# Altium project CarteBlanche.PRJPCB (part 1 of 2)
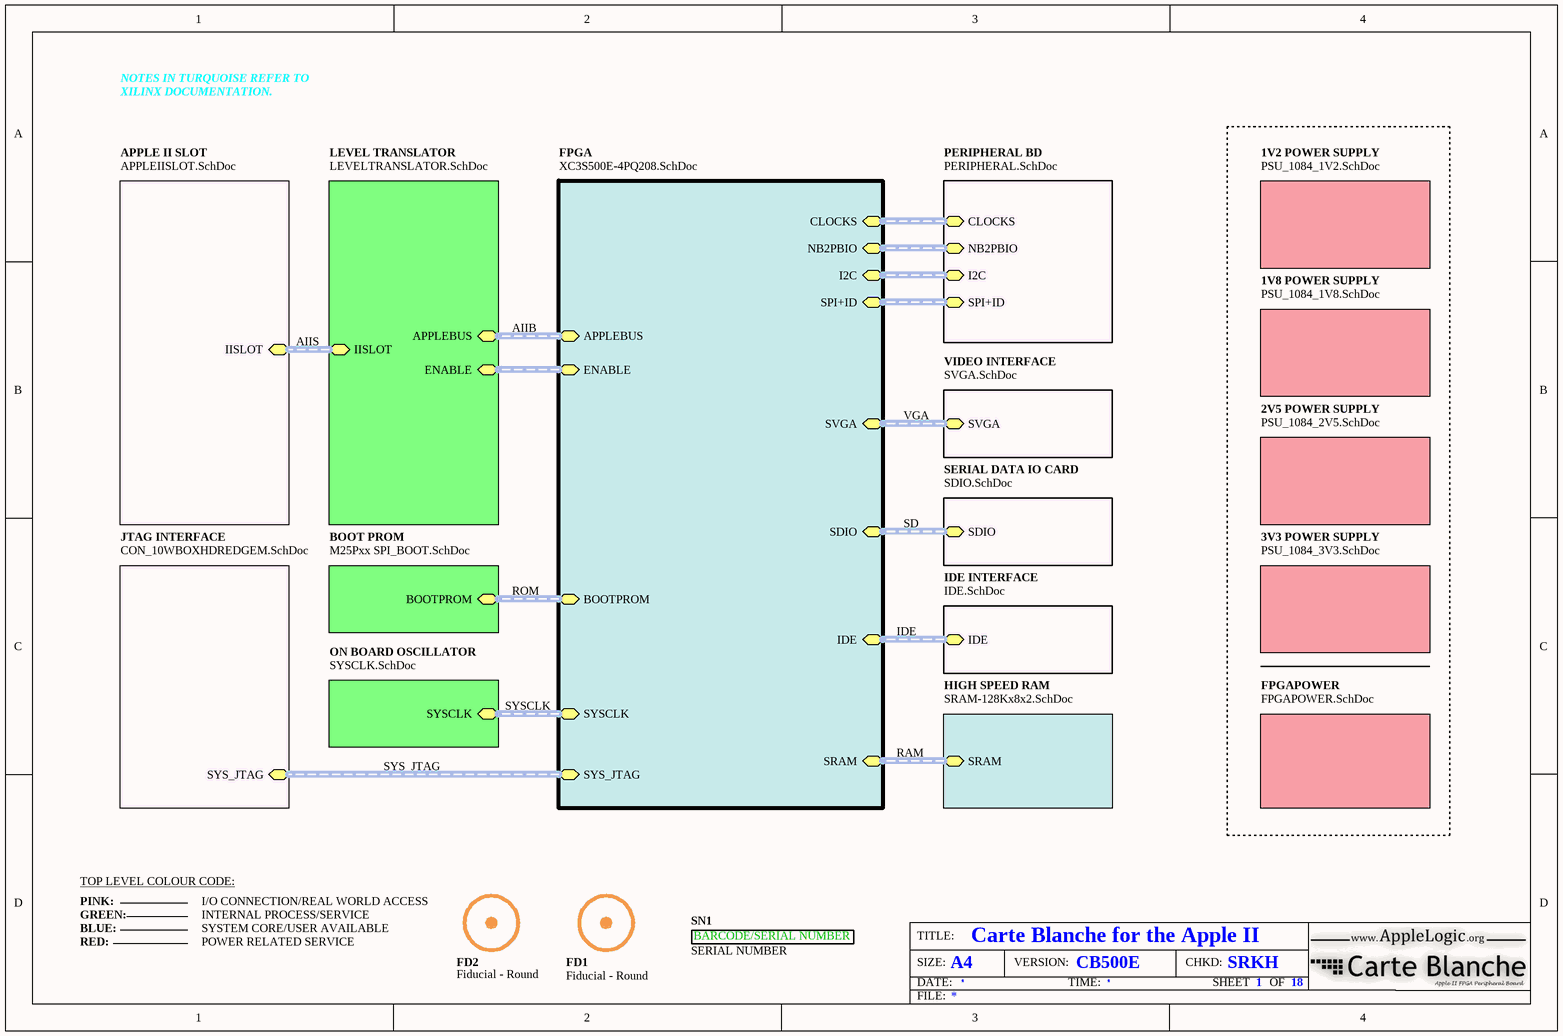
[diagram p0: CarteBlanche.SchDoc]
18 sheets, 155 parts. Net scope: hierarchical (ports join the sheet entries above them; power ports are global).
Sheets:
  CarteBlanche.SchDoc
    APPLE II SLOT = APPLEIISLOT.SchDoc
    JTAG INTERFACE = CON_10WBOXHDREDGEM.SchDoc
    FPGA = XC3S500E-4PQ208.SchDoc
    LEVEL TRANSLATOR = LEVELTRANSLATOR.SchDoc
    PERIPHERAL BD = PERIPHERAL.SchDoc
    1V2 POWER SUPPLY = PSU_1084_1V2.SchDoc
    1V8 POWER SUPPLY = PSU_1084_1V8.SchDoc
    2V5 POWER SUPPLY = PSU_1084_2V5.SchDoc
    3V3 POWER SUPPLY = PSU_1084_3V3.SchDoc
    FPGAPOWER = FPGAPOWER.SchDoc
    HIGH SPEED RAM = SRAM-128Kx8x2.SchDoc
    BOOT PROM = M25Pxx SPI_BOOT.SchDoc
    VIDEO INTERFACE = SVGA.SchDoc
      SVGA DB15 CONNECTOR = SVGAIO.SchDoc
    SERIAL DATA IO CARD = SDIO.SchDoc
    IDE INTERFACE = IDE.SchDoc
    ON BOARD OSCILLATOR = SYSCLK.SchDoc

## Sheet CarteBlanche.SchDoc: Carte Blanche for the Apple II
size A4; PageSetup: Record=PageOptions|CenterHorizontal=True|CenterVertical=True|PrintScale=1.42|XCorrection=1.00|YCorrection=1.00|PrintKind=0|BorderSize=5000000|LeftOffset=0|BottomOffset=0|Orientation=2|PaperLength=1000|PaperWidth=1000|Scale=100|PaperSource=15|PrintQuality=4000|MediaType=1|DitherType=10|PaperKind=A3|PrintScaleMode=1; CheckedBy: SRKH; Author: SRKH; Engineer: SRKH; DocumentNumber: 1; Revision: CB500E; SheetNumber: 1; SheetTotal: 18; DrawnBy: SRKH; Address1: WWW.APPLELOGIC.ORG

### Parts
FD1  Fiducial - Round  [FIDUCIAL ROUND]
FD2  Fiducial - Round  [FIDUCIAL ROUND]
SN1  SERIAL NUMBER  [SERIAL_NO2]  (no BOM)

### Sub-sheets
1V2 POWER SUPPLY = PSU_1084_1V2.SchDoc: no entries
1V8 POWER SUPPLY = PSU_1084_1V8.SchDoc: no entries
2V5 POWER SUPPLY = PSU_1084_2V5.SchDoc: no entries
3V3 POWER SUPPLY = PSU_1084_3V3.SchDoc: no entries
APPLE II SLOT = APPLEIISLOT.SchDoc: IISLOT (harness AIISLOT)
BOOT PROM = M25Pxx SPI_BOOT.SchDoc: BOOTPROM (harness BOOTPROM)
FPGA = XC3S500E-4PQ208.SchDoc: SYS_JTAG (harness SYS_JTAG), APPLEBUS (harness AIISLOT), NB2PBIO (harness NB2PBIO), SPI+ID (harness SPI+ID), I2C (harness I2C), CLOCKS (harness CLOCKS), SRAM (harness SRAM), BOOTPROM (harness BOOTPROM), SVGA (harness SVGA), IDE (harness IDE), SDIO (harness SDIO), SYSCLK (harness SYSCLK), ENABLE (harness ENABLE)
FPGAPOWER = FPGAPOWER.SchDoc: no entries
HIGH SPEED RAM = SRAM-128Kx8x2.SchDoc: SRAM (harness SRAM)
IDE INTERFACE = IDE.SchDoc: IDE (harness IDE)
JTAG INTERFACE = CON_10WBOXHDREDGEM.SchDoc: SYS_JTAG (harness SYS_JTAG)
LEVEL TRANSLATOR = LEVELTRANSLATOR.SchDoc: ENABLE (harness ENABLE), IISLOT (harness AIISLOT), APPLEBUS (harness AIISLOT)
ON BOARD OSCILLATOR = SYSCLK.SchDoc: SYSCLK (harness SYSCLK)
PERIPHERAL BD = PERIPHERAL.SchDoc: NB2PBIO (harness NB2PBIO), SPI+ID (harness SPI+ID), I2C (harness I2C), CLOCKS (harness CLOCKS)
SERIAL DATA IO CARD = SDIO.SchDoc: SDIO (harness SDIO)
VIDEO INTERFACE = SVGA.SchDoc: SVGA (harness SVGA)

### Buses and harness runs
harness AIIB = sheet FPGA/APPLEBUS = sheet LEVEL TRANSLATOR/APPLEBUS
harness AIIS = sheet APPLE II SLOT/IISLOT = sheet LEVEL TRANSLATOR/IISLOT
harness IDE = sheet FPGA/IDE = sheet IDE INTERFACE/IDE
harness RAM = sheet FPGA/SRAM = sheet HIGH SPEED RAM/SRAM
harness ROM = sheet BOOT PROM/BOOTPROM = sheet FPGA/BOOTPROM
harness SD = sheet FPGA/SDIO = sheet SERIAL DATA IO CARD/SDIO
harness sheet FPGA/CLOCKS = sheet PERIPHERAL BD/CLOCKS
harness sheet FPGA/ENABLE = sheet LEVEL TRANSLATOR/ENABLE
harness sheet FPGA/I2C = sheet PERIPHERAL BD/I2C
harness sheet FPGA/NB2PBIO = sheet PERIPHERAL BD/NB2PBIO
harness sheet FPGA/SPI+ID = sheet PERIPHERAL BD/SPI+ID
harness SYS_JTAG = sheet FPGA/SYS_JTAG = sheet JTAG INTERFACE/SYS_JTAG
harness SYSCLK = sheet FPGA/SYSCLK = sheet ON BOARD OSCILLATOR/SYSCLK
harness VGA = sheet FPGA/SVGA = sheet VIDEO INTERFACE/SVGA

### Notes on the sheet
- NOTES IN TURQUOISE REFER TO
- XILINX DOCUMENTATION.
- TOP LEVEL COLOUR CODE:
- PINK:
- GREEN:
- I/O CONNECTION/REAL WORLD ACCESS
- INTERNAL PROCESS/SERVICE
- BLUE:
- RED:
- SYSTEM CORE/USER AVAILABLE
- POWER RELATED SERVICE

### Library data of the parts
FD1 FD2 = FIDUCIAL ROUND: Fiducial - Round 1.5mm Top-Bottom

## Sheet APPLEIISLOT.SchDoc: APPLE II BUS INTERFACE
size A4; PageSetup: Record=PageOptions|CenterHorizontal=True|CenterVertical=True|PrintScale=0.73|XCorrection=1.00|YCorrection=1.00|PrintKind=0|BorderSize=5000000|LeftOffset=0|BottomOffset=0|Orientation=2|PaperLength=1000|PaperWidth=1000|Scale=100|PaperSource=7|PrintQuality=-4|MediaType=1|DitherType=10|PaperKind=A3|PrintScaleMode=1; CheckedBy: SRKH; Author: SRKH; Engineer: SRKH; DocumentNumber: 5; Revision: CB500E; SheetNumber: 5; SheetTotal: 18; DrawnBy: SRKH; Address1: WWW.APPLELOGIC.ORG
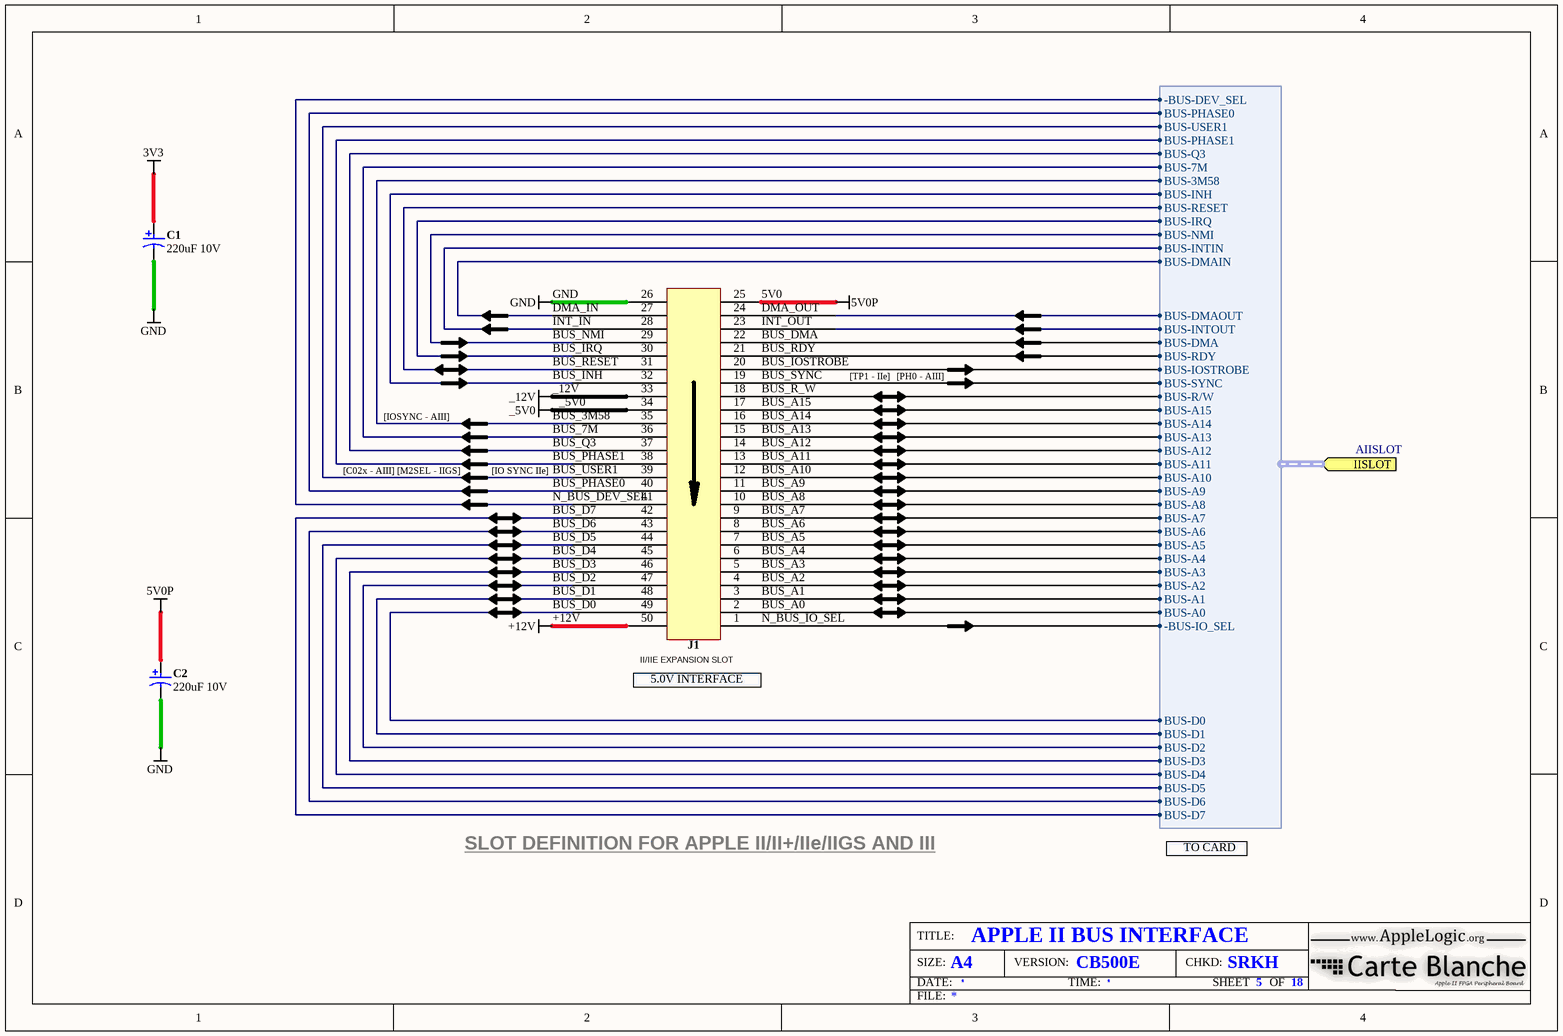
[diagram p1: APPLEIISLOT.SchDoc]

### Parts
C1  220uF 10V  [CAPC7343-STAR]
C2  220uF 10V  [CAPC7343-STAR]
J1  II/IIE EXPANSION SLOT  [APPLE II EDGE CONNECTOR]  (no BOM)

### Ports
IISLOT (harness AIISLOT)

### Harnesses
AIISLOT: -BUS-DEV_SEL, BUS-PHASE0, BUS-USER1, BUS-PHASE1, BUS-Q3, BUS-7M, BUS-3M58, BUS-INH, BUS-RESET, BUS-IRQ, BUS-NMI, BUS-DMA, BUS-RDY, BUS-IOSTROBE, BUS-SYNC, BUS-R/W, BUS-A15, BUS-A14, BUS-A13, BUS-A12, BUS-A11, BUS-A10, BUS-A9, BUS-A8, BUS-A7, BUS-A6, BUS-A5, BUS-A4, BUS-A3, BUS-A2, BUS-A1, BUS-A0, -BUS-IO_SEL, BUS-D0, BUS-D1, BUS-D2, BUS-D3, BUS-D4, BUS-D5, BUS-D6, BUS-D7, BUS-DMAIN, BUS-DMAOUT, BUS-INTIN, BUS-INTOUT

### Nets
3V3: C1.1
5V0P: C2.1 J1.25  [also labelled 5V0]
+12V: J1.50
_5V0: J1.34
_12V: J1.33
GND: C1.2 C2.2 J1.26
BUS_3M58: J1.35 ; port IISLOT.BUS-3M58  [project net AIIS.BUS-3M58]
BUS_7M: J1.36 ; port IISLOT.BUS-7M  [project net AIIS.BUS-7M]
BUS_A0: J1.2 ; port IISLOT.BUS-A0  [project net AIIS.BUS-A0]
BUS_A1: J1.3 ; port IISLOT.BUS-A1  [project net AIIS.BUS-A1]
BUS_A2: J1.4 ; port IISLOT.BUS-A2  [project net AIIS.BUS-A2]
BUS_A3: J1.5 ; port IISLOT.BUS-A3  [project net AIIS.BUS-A3]
BUS_A4: J1.6 ; port IISLOT.BUS-A4  [project net AIIS.BUS-A4]
BUS_A5: J1.7 ; port IISLOT.BUS-A5  [project net AIIS.BUS-A5]
BUS_A6: J1.8 ; port IISLOT.BUS-A6  [project net AIIS.BUS-A6]
BUS_A7: J1.9 ; port IISLOT.BUS-A7  [project net AIIS.BUS-A7]
BUS_A8: J1.10 ; port IISLOT.BUS-A8  [project net AIIS.BUS-A8]
BUS_A9: J1.11 ; port IISLOT.BUS-A9  [project net AIIS.BUS-A9]
BUS_A10: J1.12 ; port IISLOT.BUS-A10  [project net AIIS.BUS-A10]
BUS_A11: J1.13 ; port IISLOT.BUS-A11  [project net AIIS.BUS-A11]
BUS_A12: J1.14 ; port IISLOT.BUS-A12  [project net AIIS.BUS-A12]
BUS_A13: J1.15 ; port IISLOT.BUS-A13  [project net AIIS.BUS-A13]
BUS_A14: J1.16 ; port IISLOT.BUS-A14  [project net AIIS.BUS-A14]
BUS_A15: J1.17 ; port IISLOT.BUS-A15  [project net AIIS.BUS-A15]
BUS_D0: J1.49 ; port IISLOT.BUS-D0  [project net AIIS.BUS-D0]
BUS_D1: J1.48 ; port IISLOT.BUS-D1  [project net AIIS.BUS-D1]
BUS_D2: J1.47 ; port IISLOT.BUS-D2  [project net AIIS.BUS-D2]
BUS_D3: J1.46 ; port IISLOT.BUS-D3  [project net AIIS.BUS-D3]
BUS_D4: J1.45 ; port IISLOT.BUS-D4  [project net AIIS.BUS-D4]
BUS_D5: J1.44 ; port IISLOT.BUS-D5  [project net AIIS.BUS-D5]
BUS_D6: J1.43 ; port IISLOT.BUS-D6  [project net AIIS.BUS-D6]
BUS_D7: J1.42 ; port IISLOT.BUS-D7  [project net AIIS.BUS-D7]
BUS_DMA: J1.22 ; port IISLOT.BUS-DMA  [project net AIIS.BUS-DMA]
BUS_INH: J1.32 ; port IISLOT.BUS-INH  [project net AIIS.BUS-INH]
BUS_IOSTROBE: J1.20 ; port IISLOT.BUS-IOSTROBE  [project net AIIS.BUS-IOSTROBE]
BUS_IRQ: J1.30 ; port IISLOT.BUS-IRQ  [project net AIIS.BUS-IRQ]
BUS_NMI: J1.29 ; port IISLOT.BUS-NMI  [project net AIIS.BUS-NMI]
BUS_PHASE0: J1.40 ; port IISLOT.BUS-PHASE0  [project net AIIS.BUS-PHASE0]
BUS_PHASE1: J1.38 ; port IISLOT.BUS-PHASE1  [project net AIIS.BUS-PHASE1]
BUS_Q3: J1.37 ; port IISLOT.BUS-Q3  [project net AIIS.BUS-Q3]
BUS_R_W: J1.18 ; port IISLOT.BUS-R/W  [project net AIIS.BUS-R/W]
BUS_RDY: J1.21 ; port IISLOT.BUS-RDY  [project net AIIS.BUS-RDY]
BUS_RESET: J1.31 ; port IISLOT.BUS-RESET  [project net AIIS.BUS-RESET]
BUS_SYNC: J1.19 ; port IISLOT.BUS-SYNC  [project net AIIS.BUS-SYNC]
BUS_USER1: J1.39 ; port IISLOT.BUS-USER1  [project net AIIS.BUS-USER1]
DMA_IN: J1.27 ; port IISLOT.BUS-DMAIN  [project net AIIS.BUS-DMAIN]
DMA_OUT: J1.24 ; port IISLOT.BUS-DMAOUT  [project net AIIS.BUS-DMAOUT]
INT_IN: J1.28 ; port IISLOT.BUS-INTIN  [project net AIIS.BUS-INTIN]
INT_OUT: J1.23 ; port IISLOT.BUS-INTOUT  [project net AIIS.BUS-INTOUT]
N_BUS_DEV_SEL: J1.41 ; port IISLOT.-BUS-DEV_SEL  [project net AIIS.-BUS-DEV_SEL]
N_BUS_IO_SEL: J1.1 ; port IISLOT.-BUS-IO_SEL  [project net AIIS.-BUS-IO_SEL]

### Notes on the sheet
- [TP1 - IIe]
- [PH0 - AIII]
- [IOSYNC - AIII]
- [C02x - AIII]
- [M2SEL - IIGS]
- [IO SYNC IIe]
- (near J1) 5.0V INTERFACE
- SLOT DEFINITION FOR APPLE II/II+/IIe/IIGS AND III
- TO CARD

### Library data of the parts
C1 C2 = CAP-P: Capacitor, Tantalum, 220uF 10% 10V MCCT-D (7343-31)
J1 = CONNECTOR EDGE 25X2_0

## Sheet CON_10WBOXHDREDGEM.SchDoc: JTAG INTERFACE
size A4; PageSetup: Record=PageOptions|CenterHorizontal=True|CenterVertical=True|PrintScale=0.50|XCorrection=1.00|YCorrection=1.00|PrintKind=0|BorderSize=5000000|LeftOffset=0|BottomOffset=0|Orientation=2|PaperLength=1000|PaperWidth=1000|Scale=100|PaperSource=7|PrintQuality=600|MediaType=1|DitherType=10|PaperKind=12" x 18"|PrintScaleMode=1; CheckedBy: SRKH; Author: SRKH; Engineer: SRKH; DocumentNumber: 2; Revision: CB500E; SheetNumber: 2; SheetTotal: 18; DrawnBy: SRKH; Address1: WWW.APPLELOGIC.ORG
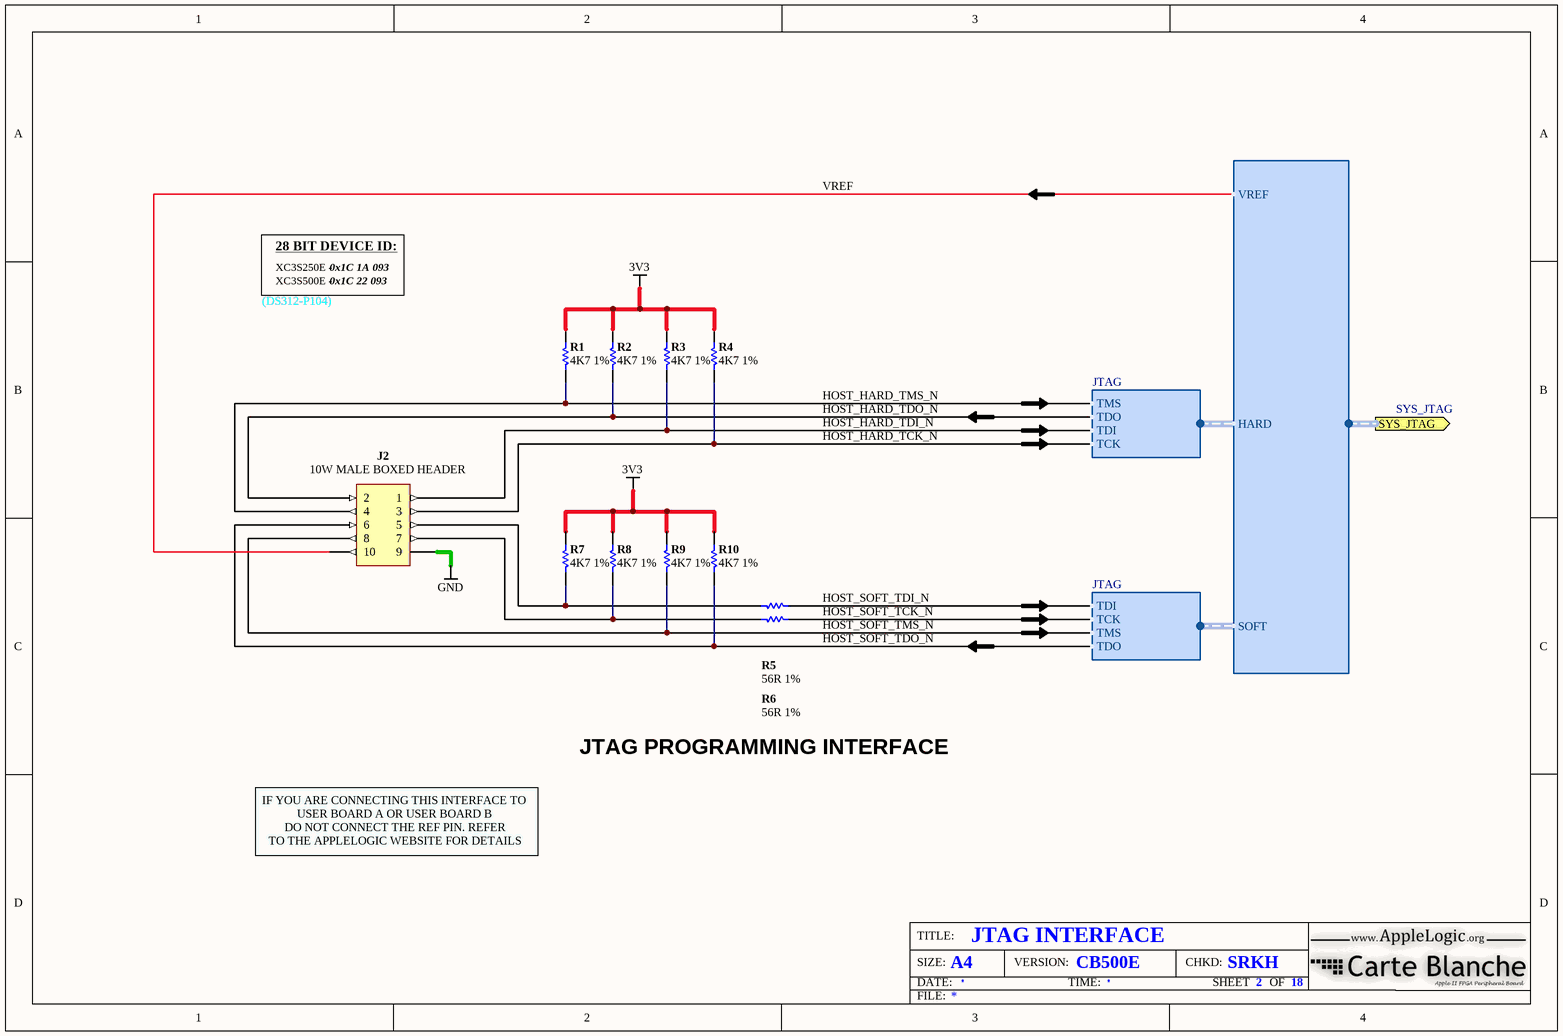
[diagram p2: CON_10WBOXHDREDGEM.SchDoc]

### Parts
J2  10W MALE BOXED HEADER  [918510X323]
R1  4K7 1%  [RESC1005-STAR]
R2  4K7 1%  [RESC1005-STAR]
R3  4K7 1%  [RESC1005-STAR]
R4  4K7 1%  [RESC1005-STAR]
R5  56R 1%  [RESC1005-STAR]
R6  56R 1%  [RESC1005-STAR]
R7  4K7 1%  [RESC1005-STAR]
R8  4K7 1%  [RESC1005-STAR]
R9  4K7 1%  [RESC1005-STAR]
R10  4K7 1%  [RESC1005-STAR]

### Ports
SYS_JTAG (harness SYS_JTAG)

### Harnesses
JTAG: TMS, TDO, TDI, TCK
SYS_JTAG: HARD, SOFT, VREF

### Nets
3V3: R1.1 R2.1 R3.1 R4.1 R7.1 R8.1 R9.1 R10.1
GND: J2.9
HOST_HARD_TCK_N: J2.3 R4.2 ; harness JTAG.TCK
HOST_HARD_TDI_N: J2.1 R3.2 ; harness JTAG.TDI
HOST_HARD_TDO_N: J2.2 R2.2 ; harness JTAG.TDO
HOST_HARD_TMS_N: J2.4 R1.2 ; harness JTAG.TMS
HOST_SOFT_TCK_N: R6.2 ; harness JTAG.TCK
HOST_SOFT_TDI_N: R5.2 ; harness JTAG.TDI
HOST_SOFT_TDO_N: J2.6 R10.2 ; harness JTAG.TDO
HOST_SOFT_TMS_N: J2.8 R9.2 ; harness JTAG.TMS
VREF: J2.10 ; port SYS_JTAG.VREF  [project net SYS_JTAG.VREF]
NetJ2_5: J2.5 R5.1 R7.2
NetJ2_7: J2.7 R6.1 R8.2

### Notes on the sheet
- 28 BIT DEVICE ID:
- (DS312-P104)
- XC3S250E -
- XC3S500E -
- 0x1C 1A 093
- 0x1C 22 093
- JTAG PROGRAMMING INTERFACE
- IF YOU ARE CONNECTING THIS INTERFACE TO
- TO THE APPLELOGIC WEBSITE FOR DETAILS
- DO NOT CONNECT THE REF PIN. REFER
- USER BOARD A OR USER BOARD B

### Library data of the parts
J2 = CON-IDC-2x5-M-RA: Header IDC, 2x5 Pin Right-Angle 2.54mm Pitch (Boxed-Male)
R1-R10 = RES: Resistor, 4K7 1% 0402 (1005)

## Sheet XC3S500E-4PQ208.SchDoc: CARTE BLANCHE FPGA
size A2; PageSetup: Record=PageOptions|CenterHorizontal=True|CenterVertical=True|PrintScale=1.42|XCorrection=1.00|YCorrection=1.00|PrintKind=0|BorderSize=5000000|LeftOffset=0|BottomOffset=0|Orientation=2|PaperLength=1000|PaperWidth=1000|Scale=100|PaperSource=15|PrintQuality=4000|MediaType=1|DitherType=10|PaperKind=A3|PrintScaleMode=1; CheckedBy: SRKH; Author: SRKH; Engineer: SRKH; DocumentNumber: 17; Revision: CB500E; SheetNumber: 17; SheetTotal: 18; DrawnBy: SRKH; Address1: WWW.APPLELOGIC.ORG
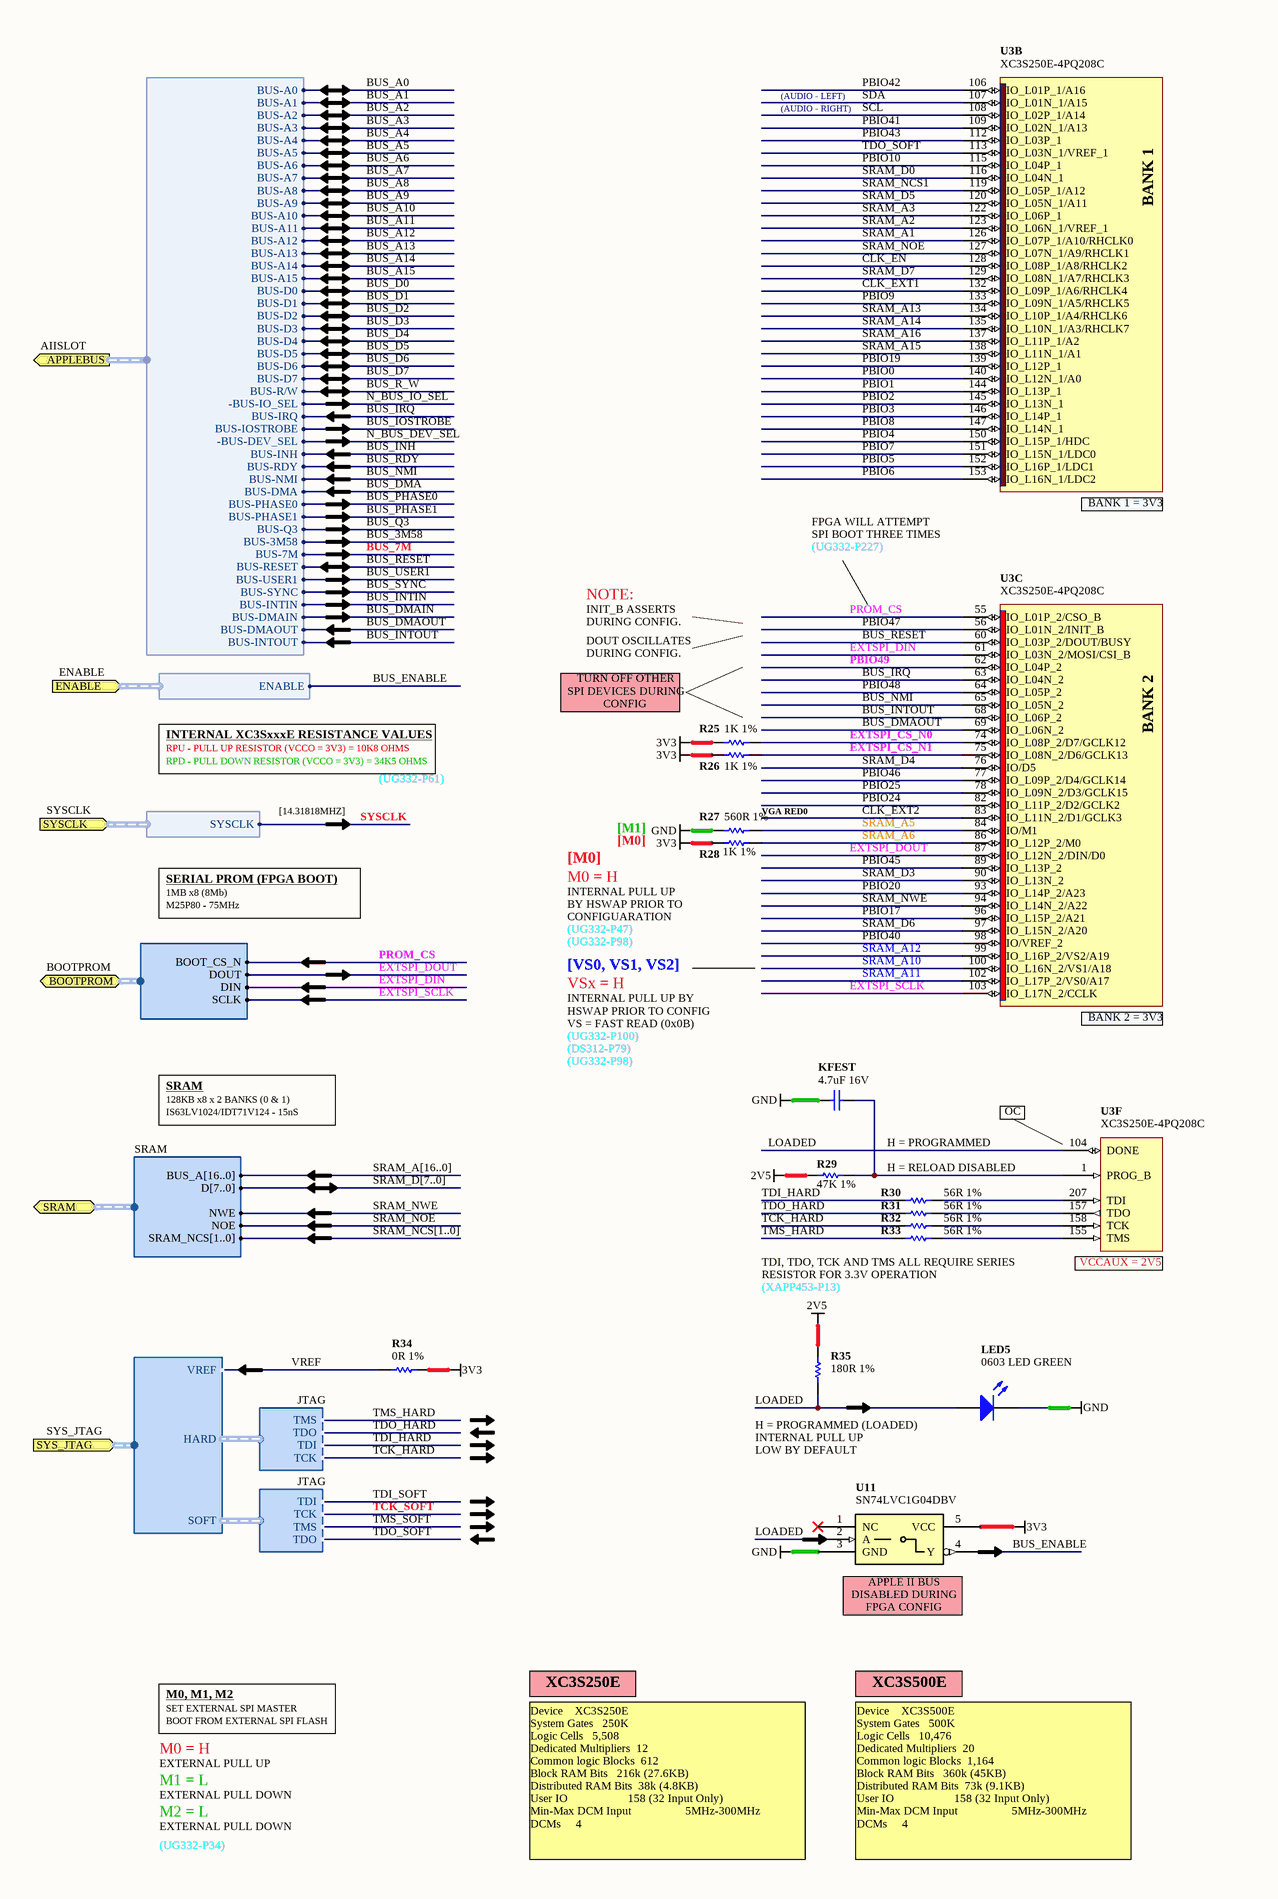
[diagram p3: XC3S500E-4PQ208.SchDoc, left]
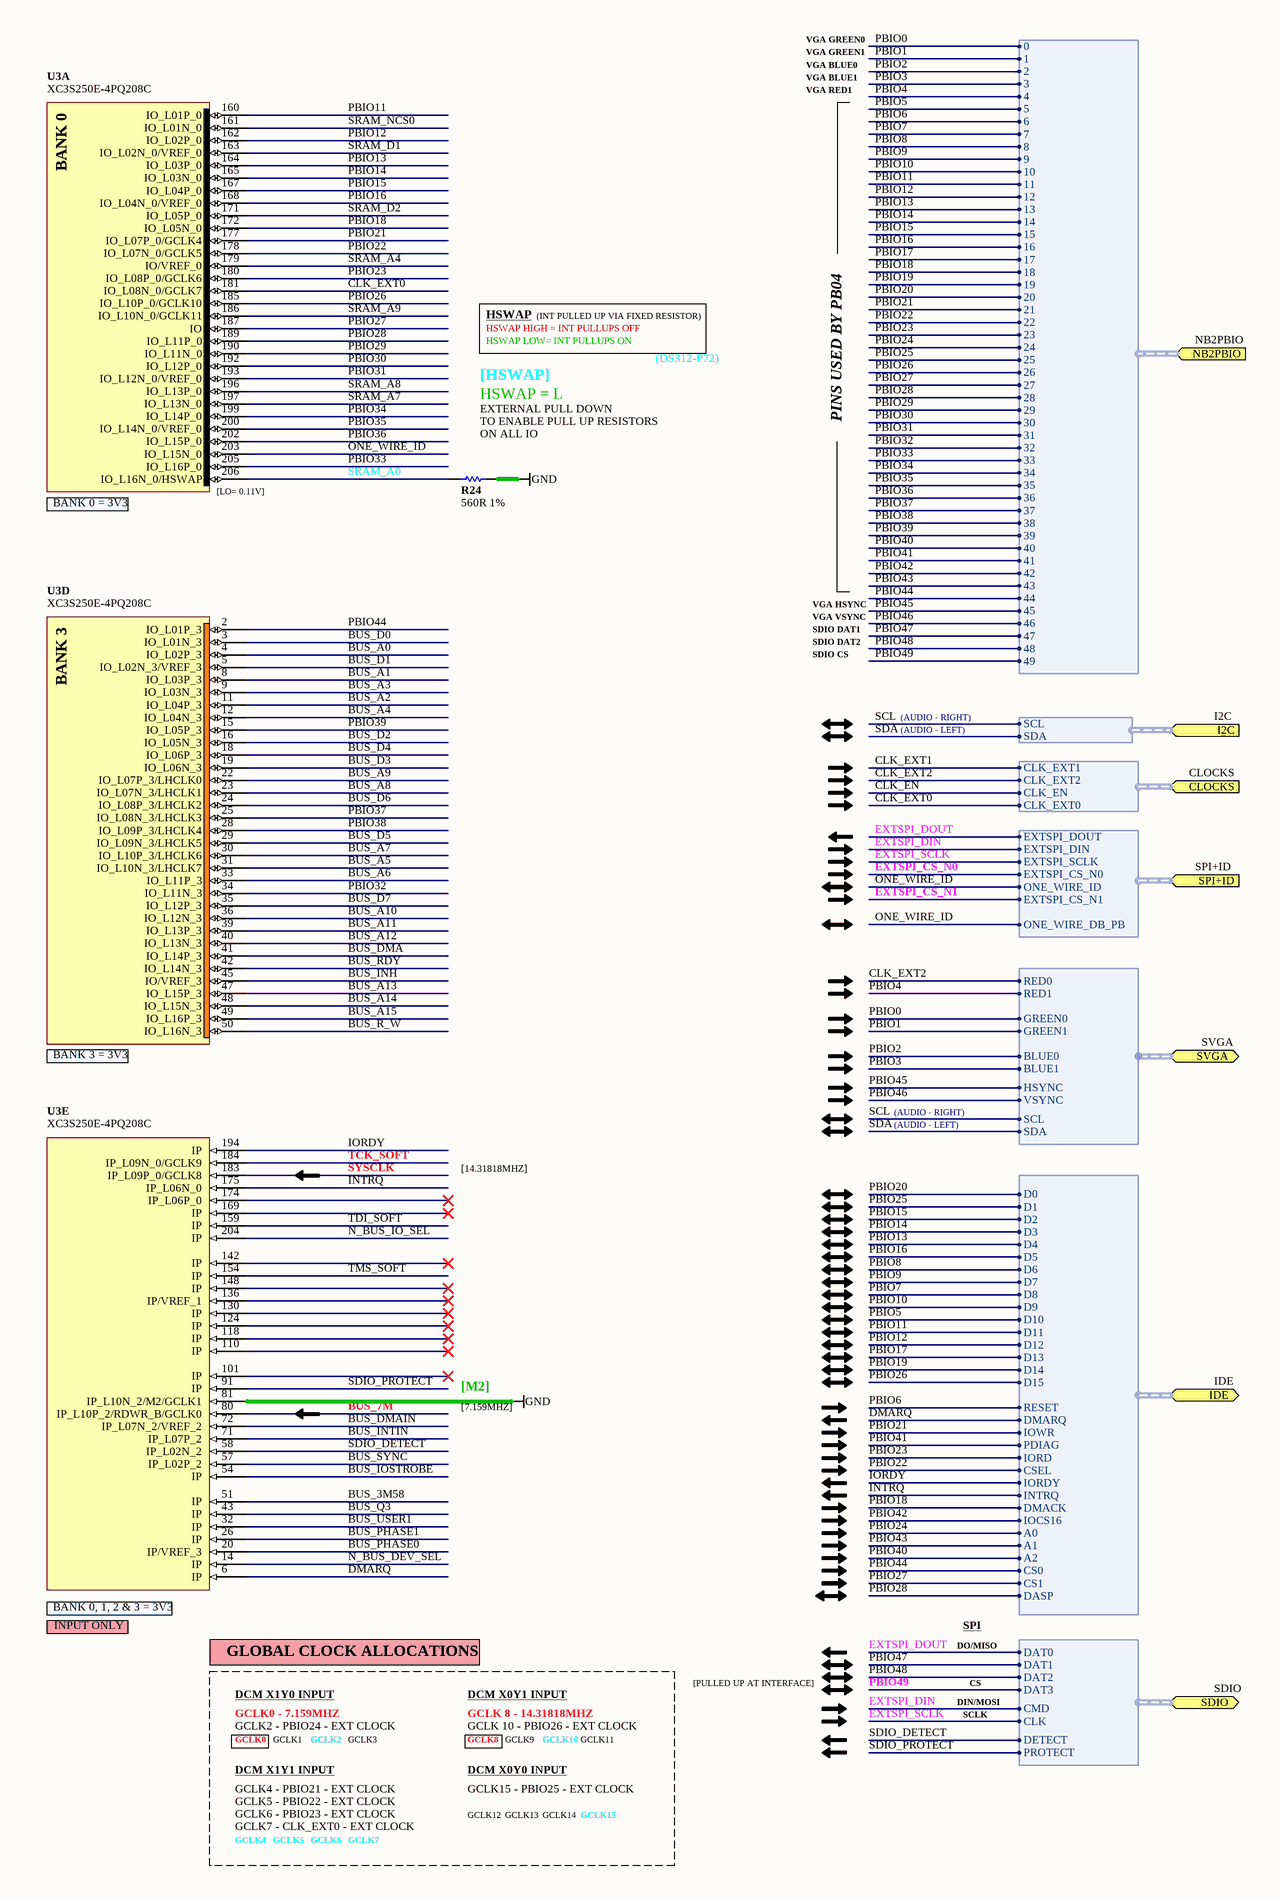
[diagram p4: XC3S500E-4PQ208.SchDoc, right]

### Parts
(Parts that share a designator on the sheet are numbered #1, #2 ... from top to bottom, then left to right.)
KFEST  4.7uF 16V  [CAPC1005-STAR]
LED5  0603 LED GREEN  [0603LED_Kingbright_Green]
R24  560R 1%  [RESC1005-STAR]
R25  1K 1%  [RESC1005-STAR]
R26  1K 1%  [RESC1005-STAR]
R27  560R 1%  [RESC1005-STAR]
R28  1K 1%  [RESC1005-STAR]
R29  47K 1%  [RESC1005-STAR]
R30  56R 1%  [RESC1005-STAR]
R31  56R 1%  [RESC1005-STAR]
R32  56R 1%  [RESC1005-STAR]
R33  56R 1%  [RESC1005-STAR]
R34  0R 1%  [RESC1005-STAR]
R35  180R 1%  [RESC1005-STAR]
U3#1  XC3S250E-4PQ208C  [PQ208_N]  (parts A,B,C,D,E,F of 8)
U11  SN74LVC1G04DBV  [SOT95P280-5]

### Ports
APPLEBUS (harness AIISLOT), BOOTPROM (harness BOOTPROM), CLOCKS (harness CLOCKS), ENABLE (harness ENABLE), I2C (harness I2C), IDE (harness IDE), NB2PBIO (harness NB2PBIO), SDIO (harness SDIO), SPI+ID (harness SPI+ID), SRAM (harness SRAM), SVGA (harness SVGA), SYS_JTAG (harness SYS_JTAG), SYSCLK (harness SYSCLK)

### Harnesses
AIISLOT: -BUS-DEV_SEL, BUS-PHASE0, BUS-USER1, BUS-PHASE1, BUS-Q3, BUS-7M, BUS-3M58, BUS-INH, BUS-RESET, BUS-IRQ, BUS-NMI, BUS-DMA, BUS-RDY, BUS-IOSTROBE, BUS-SYNC, BUS-R/W, BUS-A15, BUS-A14, BUS-A13, BUS-A12, BUS-A11, BUS-A10, BUS-A9, BUS-A8, BUS-A7, BUS-A6, BUS-A5, BUS-A4, BUS-A3, BUS-A2, BUS-A1, BUS-A0, -BUS-IO_SEL, BUS-D0, BUS-D1, BUS-D2, BUS-D3, BUS-D4, BUS-D5, BUS-D6, BUS-D7, BUS-DMAIN, BUS-INTIN, BUS-DMAOUT, BUS-INTOUT
I2C: SCL, SDA
CLOCKS: CLK_EXT2, CLK_EXT0, CLK_EXT1, CLK_EN
SPI+ID: EXTSPI_DIN, EXTSPI_CS_N0, EXTSPI_DOUT, EXTSPI_SCLK, ONE_WIRE_ID, EXTSPI_CS_N1, ONE_WIRE_DB_PB
NB2PBIO: 0, 1, 2, 3, 4, 5, 6, 7, 8, 9, 10, 11, 12, 13, 14, 15, 16, 17, 18, 19, 20, 21, 22, 23, 24, 25, 26, 27, 28, 29, 30, 31, 32, 33, 34, 35, 36, 37, 38, 39, 40, 41, 42, 43, 44, 45, 46, 47, 48, 49
JTAG: TMS, TDO, TDI, TCK
SYS_JTAG: HARD, SOFT, VREF
BOOTPROM: DIN, DOUT, SCLK, BOOT_CS_N
SRAM: BUS_A[16..0], D[7..0], NWE, SRAM_NCS[1..0], NOE
IDE: CS1, A2, D3, INTRQ, IORD, IOWR, DASP, RESET, CSEL, IOCS16, DMARQ, DMACK, PDIAG, IORDY, CS0, A1, A0, D4, D5, D6, D7, D8, D9, D10, D11, D12, D13, D14, D15, D2, D1, D0
SDIO: DAT0, CMD, CLK, PROTECT, DETECT, DAT1, DAT2, DAT3
SYSCLK: SYSCLK
SVGA: BLUE0, SDA, RED0, RED1, HSYNC, VSYNC, SCL, GREEN0, GREEN1, BLUE1
ENABLE: ENABLE

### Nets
2V5: R29.2 R35.2
3V3: R25.1 R26.1 R28.1 R34.1 U11.5(VCC)
GND: KFEST.2 LED5.2(K) R24.2 R27.1 U3#1.81(IP_L10N_2/M2/GCLK1) U11.3(GND)
BUS_3M58: U3#1.51(IP) ; port APPLEBUS.BUS-3M58  [project net AIIB.BUS-3M58]
BUS_7M: U3#1.80(IP_L10P_2/RDWR_B/GCLK0) ; port APPLEBUS.BUS-7M  [project net AIIB.BUS-7M]
BUS_A0: U3#1.4(IO_L02P_3) ; port APPLEBUS.BUS-A0  [project net AIIB.BUS-A0]
BUS_A1: U3#1.8(IO_L03P_3) ; port APPLEBUS.BUS-A1  [project net AIIB.BUS-A1]
BUS_A2: U3#1.11(IO_L04P_3) ; port APPLEBUS.BUS-A2  [project net AIIB.BUS-A2]
BUS_A3: U3#1.9(IO_L03N_3) ; port APPLEBUS.BUS-A3  [project net AIIB.BUS-A3]
BUS_A4: U3#1.12(IO_L04N_3) ; port APPLEBUS.BUS-A4  [project net AIIB.BUS-A4]
BUS_A5: U3#1.31(IO_L10N_3/LHCLK7) ; port APPLEBUS.BUS-A5  [project net AIIB.BUS-A5]
BUS_A6: U3#1.33(IO_L11P_3) ; port APPLEBUS.BUS-A6  [project net AIIB.BUS-A6]
BUS_A7: U3#1.30(IO_L10P_3/LHCLK6) ; port APPLEBUS.BUS-A7  [project net AIIB.BUS-A7]
BUS_A8: U3#1.23(IO_L07N_3/LHCLK1) ; port APPLEBUS.BUS-A8  [project net AIIB.BUS-A8]
BUS_A9: U3#1.22(IO_L07P_3/LHCLK0) ; port APPLEBUS.BUS-A9  [project net AIIB.BUS-A9]
BUS_A10: U3#1.36(IO_L12N_3) ; port APPLEBUS.BUS-A10  [project net AIIB.BUS-A10]
BUS_A11: U3#1.39(IO_L13P_3) ; port APPLEBUS.BUS-A11  [project net AIIB.BUS-A11]
BUS_A12: U3#1.40(IO_L13N_3) ; port APPLEBUS.BUS-A12  [project net AIIB.BUS-A12]
BUS_A13: U3#1.47(IO_L15P_3) ; port APPLEBUS.BUS-A13  [project net AIIB.BUS-A13]
BUS_A14: U3#1.48(IO_L15N_3) ; port APPLEBUS.BUS-A14  [project net AIIB.BUS-A14]
BUS_A15: U3#1.49(IO_L16P_3) ; port APPLEBUS.BUS-A15  [project net AIIB.BUS-A15]
BUS_D0: U3#1.3(IO_L01N_3) ; port APPLEBUS.BUS-D0  [project net AIIB.BUS-D0]
BUS_D1: U3#1.5(IO_L02N_3/VREF_3) ; port APPLEBUS.BUS-D1  [project net AIIB.BUS-D1]
BUS_D2: U3#1.16(IO_L05N_3) ; port APPLEBUS.BUS-D2  [project net AIIB.BUS-D2]
BUS_D3: U3#1.19(IO_L06N_3) ; port APPLEBUS.BUS-D3  [project net AIIB.BUS-D3]
BUS_D4: U3#1.18(IO_L06P_3) ; port APPLEBUS.BUS-D4  [project net AIIB.BUS-D4]
BUS_D5: U3#1.29(IO_L09N_3/LHCLK5) ; port APPLEBUS.BUS-D5  [project net AIIB.BUS-D5]
BUS_D6: U3#1.24(IO_L08P_3/LHCLK2) ; port APPLEBUS.BUS-D6  [project net AIIB.BUS-D6]
BUS_D7: U3#1.35(IO_L12P_3) ; port APPLEBUS.BUS-D7  [project net AIIB.BUS-D7]
BUS_DMA: U3#1.41(IO_L14P_3) ; port APPLEBUS.BUS-DMA  [project net AIIB.BUS-DMA]
BUS_DMAIN: U3#1.72(IP_L07N_2/VREF_2) ; port APPLEBUS.BUS-DMAIN  [project net AIIB.BUS-DMAIN]
BUS_DMAOUT: U3#1.69(IO_L06N_2) ; port APPLEBUS.BUS-DMAOUT  [project net AIIB.BUS-DMAOUT]
BUS_ENABLE: U11.4(Y) ; port ENABLE.ENABLE
BUS_INH: U3#1.45(IO/VREF_3) ; port APPLEBUS.BUS-INH  [project net AIIB.BUS-INH]
BUS_INTIN: U3#1.71(IP_L07P_2) ; port APPLEBUS.BUS-INTIN  [project net AIIB.BUS-INTIN]
BUS_INTOUT: U3#1.68(IO_L06P_2) ; port APPLEBUS.BUS-INTOUT  [project net AIIB.BUS-INTOUT]
BUS_IOSTROBE: U3#1.54(IP) ; port APPLEBUS.BUS-IOSTROBE  [project net AIIB.BUS-IOSTROBE]
BUS_IRQ: U3#1.63(IO_L04N_2) ; port APPLEBUS.BUS-IRQ  [project net AIIB.BUS-IRQ]
BUS_NMI: U3#1.65(IO_L05N_2) ; port APPLEBUS.BUS-NMI  [project net AIIB.BUS-NMI]
BUS_PHASE0: U3#1.20(IP/VREF_3) ; port APPLEBUS.BUS-PHASE0  [project net AIIB.BUS-PHASE0]
BUS_PHASE1: U3#1.26(IP) ; port APPLEBUS.BUS-PHASE1  [project net AIIB.BUS-PHASE1]
BUS_Q3: U3#1.43(IP) ; port APPLEBUS.BUS-Q3  [project net AIIB.BUS-Q3]
BUS_R_W: U3#1.50(IO_L16N_3) ; port APPLEBUS.BUS-R/W  [project net AIIB.BUS-R/W]
BUS_RDY: U3#1.42(IO_L14N_3) ; port APPLEBUS.BUS-RDY  [project net AIIB.BUS-RDY]
BUS_RESET: U3#1.60(IO_L03P_2/DOUT/BUSY) ; port APPLEBUS.BUS-RESET  [project net AIIB.BUS-RESET]
BUS_SYNC: U3#1.57(IP_L02P_2) ; port APPLEBUS.BUS-SYNC  [project net AIIB.BUS-SYNC]
BUS_USER1: U3#1.32(IP) ; port APPLEBUS.BUS-USER1  [project net AIIB.BUS-USER1]
CLK_EN: U3#1.128(IO_L08P_1/A8/RHCLK2) ; port CLOCKS.CLK_EN
CLK_EXT0: U3#1.181(IO_L08N_0/GCLK7) ; port CLOCKS.CLK_EXT0
CLK_EXT1: U3#1.132(IO_L09P_1/A6/RHCLK4) ; port CLOCKS.CLK_EXT1
CLK_EXT2: U3#1.83(IO_L11N_2/D1/GCLK3) ; port CLOCKS.CLK_EXT2, port SVGA.RED0  [project net VGA.RED0]
DMARQ: U3#1.6(IP) ; port IDE.DMARQ  [project net IDE.DMARQ]
EXTSPI_CS_N0: R25.2 U3#1.74(IO_L08P_2/D7/GCLK12) ; port SPI+ID.EXTSPI_CS_N0
EXTSPI_CS_N1: R26.2 U3#1.75(IO_L08N_2/D6/GCLK13) ; port SPI+ID.EXTSPI_CS_N1
EXTSPI_DIN: U3#1.61(IO_L03N_2/MOSI/CSI_B) ; port SPI+ID.EXTSPI_DIN, port BOOTPROM.DIN, port SDIO.CMD  [project net ROM.DIN]
EXTSPI_DOUT: U3#1.87(IO_L12N_2/DIN/D0) ; port SPI+ID.EXTSPI_DOUT, port BOOTPROM.DOUT, port SDIO.DAT0  [project net ROM.DOUT]
EXTSPI_SCLK: U3#1.103(IO_L17N_2/CCLK) ; port SPI+ID.EXTSPI_SCLK, port BOOTPROM.SCLK, port SDIO.CLK  [project net ROM.SCLK]
INTRQ: U3#1.175(IP_L06N_0) ; port IDE.INTRQ  [project net IDE.INTRQ]
IORDY: U3#1.194(IP) ; port IDE.IORDY  [project net IDE.IORDY]
LOADED: LED5.1(A) R35.1 U3#1.104(DONE) U11.2(A)
N_BUS_DEV_SEL: U3#1.14(IP) ; port APPLEBUS.-BUS-DEV_SEL  [project net AIIB.-BUS-DEV_SEL]
N_BUS_IO_SEL: U3#1.204(IP) ; port APPLEBUS.-BUS-IO_SEL  [project net AIIB.-BUS-IO_SEL]
ONE_WIRE_ID: U3#1.203(IO_L15N_0) ; port SPI+ID.ONE_WIRE_ID, port SPI+ID.ONE_WIRE_DB_PB  [project net ONE_WIRE_DB_PB]
PBIO0: U3#1.140(IO_L12N_1/A0) ; port NB2PBIO.0, port SVGA.GREEN0  [project net VGA.GREEN0]
PBIO1: U3#1.144(IO_L13P_1) ; port NB2PBIO.1, port SVGA.GREEN1  [project net VGA.GREEN1]
PBIO2: U3#1.145(IO_L13N_1) ; port NB2PBIO.2, port SVGA.BLUE0  [project net VGA.BLUE0]
PBIO3: U3#1.146(IO_L14P_1) ; port NB2PBIO.3, port SVGA.BLUE1  [project net VGA.BLUE1]
PBIO4: U3#1.150(IO_L15P_1/HDC) ; port NB2PBIO.4, port SVGA.RED1  [project net VGA.RED1]
PBIO5: U3#1.152(IO_L16P_1/LDC1) ; port NB2PBIO.5, port IDE.D10  [project net IDE.D10]
PBIO6: U3#1.153(IO_L16N_1/LDC2) ; port NB2PBIO.6, port IDE.RESET  [project net IDE.RESET]
PBIO7: U3#1.151(IO_L15N_1/LDC0) ; port NB2PBIO.7, port IDE.D8  [project net IDE.D8]
PBIO8: U3#1.147(IO_L14N_1) ; port NB2PBIO.8, port IDE.D6  [project net IDE.D6]
PBIO9: U3#1.133(IO_L09N_1/A5/RHCLK5) ; port NB2PBIO.9, port IDE.D7  [project net IDE.D7]
PBIO10: U3#1.115(IO_L04P_1) ; port NB2PBIO.10, port IDE.D9  [project net IDE.D9]
PBIO11: U3#1.160(IO_L01P_0) ; port NB2PBIO.11, port IDE.D11  [project net IDE.D11]
PBIO12: U3#1.162(IO_L02P_0) ; port NB2PBIO.12, port IDE.D12  [project net IDE.D12]
PBIO13: U3#1.164(IO_L03P_0) ; port NB2PBIO.13, port IDE.D4  [project net IDE.D4]
PBIO14: U3#1.165(IO_L03N_0) ; port NB2PBIO.14, port IDE.D3  [project net IDE.D3]
PBIO15: U3#1.167(IO_L04P_0) ; port NB2PBIO.15, port IDE.D2  [project net IDE.D2]
PBIO16: U3#1.168(IO_L04N_0/VREF_0) ; port NB2PBIO.16, port IDE.D5  [project net IDE.D5]
PBIO17: U3#1.96(IO_L15P_2/A21) ; port NB2PBIO.17, port IDE.D13  [project net IDE.D13]
PBIO18: U3#1.172(IO_L05N_0) ; port NB2PBIO.18, port IDE.DMACK  [project net IDE.DMACK]
PBIO19: U3#1.139(IO_L12P_1) ; port NB2PBIO.19, port IDE.D14  [project net IDE.D14]
PBIO20: U3#1.93(IO_L14P_2/A23) ; port NB2PBIO.20, port IDE.D0  [project net IDE.D0]
PBIO21: U3#1.177(IO_L07P_0/GCLK4) ; port NB2PBIO.21, port IDE.IOWR  [project net IDE.IOWR]
PBIO22: U3#1.178(IO_L07N_0/GCLK5) ; port NB2PBIO.22, port IDE.CSEL  [project net IDE.CSEL]
PBIO23: U3#1.180(IO_L08P_0/GCLK6) ; port NB2PBIO.23, port IDE.IORD  [project net IDE.IORD]
PBIO24: U3#1.82(IO_L11P_2/D2/GCLK2) ; port NB2PBIO.24, port IDE.A0  [project net IDE.A0]
PBIO25: U3#1.78(IO_L09N_2/D3/GCLK15) ; port NB2PBIO.25, port IDE.D1  [project net IDE.D1]
PBIO26: U3#1.185(IO_L10P_0/GCLK10) ; port NB2PBIO.26, port IDE.D15  [project net IDE.D15]
PBIO27: U3#1.187(IO) ; port NB2PBIO.27, port IDE.CS1  [project net IDE.CS1]
PBIO28: U3#1.189(IO_L11P_0) ; port NB2PBIO.28, port IDE.DASP  [project net IDE.DASP]
PBIO29: U3#1.190(IO_L11N_0) ; port NB2PBIO.29
PBIO30: U3#1.192(IO_L12P_0) ; port NB2PBIO.30
PBIO31: U3#1.193(IO_L12N_0/VREF_0) ; port NB2PBIO.31
PBIO32: U3#1.34(IO_L11N_3) ; port NB2PBIO.32
PBIO33: U3#1.205(IO_L16P_0) ; port NB2PBIO.33
PBIO34: U3#1.199(IO_L14P_0) ; port NB2PBIO.34
PBIO35: U3#1.200(IO_L14N_0/VREF_0) ; port NB2PBIO.35
PBIO36: U3#1.202(IO_L15P_0) ; port NB2PBIO.36
PBIO37: U3#1.25(IO_L08N_3/LHCLK3) ; port NB2PBIO.37
PBIO38: U3#1.28(IO_L09P_3/LHCLK4) ; port NB2PBIO.38
PBIO39: U3#1.15(IO_L05P_3) ; port NB2PBIO.39
PBIO40: U3#1.98(IO/VREF_2) ; port NB2PBIO.40, port IDE.A2  [project net IDE.A2]
PBIO41: U3#1.109(IO_L02N_1/A13) ; port NB2PBIO.41, port IDE.PDIAG  [project net IDE.PDIAG]
PBIO42: U3#1.106(IO_L01P_1/A16) ; port NB2PBIO.42, port IDE.IOCS16  [project net IDE.IOCS16]
PBIO43: U3#1.112(IO_L03P_1) ; port NB2PBIO.43, port IDE.A1  [project net IDE.A1]
PBIO44: U3#1.2(IO_L01P_3) ; port NB2PBIO.44, port IDE.CS0  [project net IDE.CS0]
PBIO45: U3#1.89(IO_L13P_2) ; port NB2PBIO.45, port SVGA.HSYNC  [project net VGA.HSYNC]
PBIO46: U3#1.77(IO_L09P_2/D4/GCLK14) ; port NB2PBIO.46, port SVGA.VSYNC  [project net VGA.VSYNC]
PBIO47: U3#1.56(IO_L01N_2/INIT_B) ; port NB2PBIO.47, port SDIO.DAT1  [project net SD.DAT1]
PBIO48: U3#1.64(IO_L05P_2) ; port NB2PBIO.48, port SDIO.DAT2  [project net SD.DAT2]
PBIO49: U3#1.62(IO_L04P_2) ; port NB2PBIO.49, port SDIO.DAT3  [project net SD.DAT3]
PROM_CS: U3#1.55(IO_L01P_2/CSO_B) ; port BOOTPROM.BOOT_CS_N  [project net ROM.BOOT_CS_N]
SCL: U3#1.108(IO_L02P_1/A14) ; port I2C.SCL, port SVGA.SCL  [project net VGA.SCL]
SDA: U3#1.107(IO_L01N_1/A15) ; port I2C.SDA, port SVGA.SDA  [project net VGA.SDA]
SDIO_DETECT: U3#1.58(IP_L02N_2) ; port SDIO.DETECT  [project net SD.DETECT]
SDIO_PROTECT: U3#1.91(IP) ; port SDIO.PROTECT  [project net SD.PROTECT]
SRAM_A0: R24.1 U3#1.206(IO_L16N_0/HSWAP)
SRAM_A1: U3#1.126(IO_L07P_1/A10/RHCLK0)
SRAM_A2: U3#1.123(IO_L06N_1/VREF_1)
SRAM_A3: U3#1.122(IO_L06P_1)
SRAM_A4: U3#1.179(IO/VREF_0)
SRAM_A5: R27.2 U3#1.84(IO/M1)
SRAM_A6: R28.2 U3#1.86(IO_L12P_2/M0)
SRAM_A7: U3#1.197(IO_L13N_0)
SRAM_A8: U3#1.196(IO_L13P_0)
SRAM_A9: U3#1.186(IO_L10N_0/GCLK11)
SRAM_A10: U3#1.100(IO_L16N_2/VS1/A18)
SRAM_A11: U3#1.102(IO_L17P_2/VS0/A17)
SRAM_A12: U3#1.99(IO_L16P_2/VS2/A19)
SRAM_A13: U3#1.134(IO_L10P_1/A4/RHCLK6)
SRAM_A14: U3#1.135(IO_L10N_1/A3/RHCLK7)
SRAM_A15: U3#1.138(IO_L11N_1/A1)
SRAM_A16: U3#1.137(IO_L11P_1/A2)
SRAM_D0: U3#1.116(IO_L04N_1)
SRAM_D1: U3#1.163(IO_L02N_0/VREF_0)
SRAM_D2: U3#1.171(IO_L05P_0)
SRAM_D3: U3#1.90(IO_L13N_2)
SRAM_D4: U3#1.76(IO/D5)
SRAM_D5: U3#1.120(IO_L05N_1/A11)
SRAM_D6: U3#1.97(IO_L15N_2/A20)
SRAM_D7: U3#1.129(IO_L08N_1/A7/RHCLK3)
SRAM_NCS0: U3#1.161(IO_L01N_0)
SRAM_NCS1: U3#1.119(IO_L05P_1/A12)
SRAM_NOE: U3#1.127(IO_L07N_1/A9/RHCLK1) ; port SRAM.NOE  [project net RAM.NOE]
SRAM_NWE: U3#1.94(IO_L14N_2/A22) ; port SRAM.NWE  [project net RAM.NWE]
SYSCLK: U3#1.183(IP_L09P_0/GCLK8) ; port SYSCLK.SYSCLK  [project net SYSCLK.SYSCLK]
TCK_HARD: R32.1 ; harness JTAG.TCK  [project net HOST_HARD_TCK_N]
TCK_SOFT: U3#1.184(IP_L09N_0/GCLK9) ; harness JTAG.TCK  [project net HOST_SOFT_TCK_N]
TDI_HARD: R30.1 ; harness JTAG.TDI  [project net HOST_HARD_TDI_N]
TDI_SOFT: U3#1.159(IP) ; harness JTAG.TDI  [project net HOST_SOFT_TDI_N]
TDO_HARD: R31.1 ; harness JTAG.TDO  [project net HOST_HARD_TDO_N]
TDO_SOFT: U3#1.113(IO_L03N_1/VREF_1) ; harness JTAG.TDO  [project net HOST_SOFT_TDO_N]
TMS_HARD: R33.1 ; harness JTAG.TMS  [project net HOST_HARD_TMS_N]
TMS_SOFT: U3#1.154(IP) ; harness JTAG.TMS  [project net HOST_SOFT_TMS_N]
VREF: R34.2 ; port SYS_JTAG.VREF  [project net SYS_JTAG.VREF]
NetKFEST_1: KFEST.1 R29.1 U3#1.1(PROG_B)
NetR30_2: R30.2 U3#1.207(TDI)
NetR31_2: R31.2 U3#1.157(TDO)
NetR32_2: R32.2 U3#1.158(TCK)
NetR33_2: R33.2 U3#1.155(TMS)

Not connected (* = marked no-connect by the designer): U3#1 101(IP)* 110(IP)* 118(IP)* 124(IP)* 130(IP)* 136(IP/VREF_1)* 142(IP)* 148(IP)* 169(IP)* 174(IP_L06P_0)*; U11 1(NC)*

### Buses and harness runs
bus SRAM_A[16..0]
bus SRAM_D[7..0]
bus SRAM_NCS[1..0]

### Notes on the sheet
- VGA GREEN0
- VGA GREEN1
- VGA BLUE0
- (AUDIO - LEFT)
- (AUDIO - RIGHT)
- VGA BLUE1
- VGA RED1
- HSWAP
- (INT PULLED UP VIA FIXED RESISTOR)
- [HSWAP]
- HSWAP HIGH = INT PULLUPS OFF
- HSWAP LOW= INT PULLUPS ON
- (DS312-P72)
- HSWAP = L
- EXTERNAL PULL DOWN
- TO ENABLE PULL UP RESISTORS
- (near R24) ON ALL IO
- PINS USED BY PB04
- BANK 1 = 3V3
- BANK 0 = 3V3
- (near U3#1) [LO= 0.11V]
- (UG332-P227)
- SPI BOOT THREE TIMES
- FPGA WILL ATTEMPT
- NOTE:
- INIT_B ASSERTS
- DURING CONFIG.
- SDIO DAT1
- VGA VSYNC
- VGA HSYNC
- SPI DEVICES DURING
- TURN OFF OTHER
- DOUT OSCILLATES
- SDIO CS
- SDIO DAT2
- INTERNAL XC3SxxxE RESISTANCE VALUES
- RPU - PULL UP RESISTOR (VCCO = 3V3) = 10K8 OHMS
- CONFIG
- RPD - PULL DOWN RESISTOR (VCCO = 3V3) = 34K5 OHMS
- [14.31818MHZ]
- (UG332-P61)
- VGA RED0
- SERIAL PROM (FPGA BOOT)
- M0 = H
- [M0]
- [M1]
- 1MB x8 (8Mb)
- M25P80 - 75MHz
- INTERNAL PULL UP
- BY HSWAP PRIOR TO
- CONFIGUARATION
- (UG332-P47)
- (UG332-P98)
- VSx = H
- INTERNAL PULL UP BY
- [VS0, VS1, VS2]
- HSWAP PRIOR TO CONFIG
- VS = FAST READ (0x0B)
- (UG332-P100)
- (DS312-P79)
- BANK 2 = 3V3
- BANK 3 = 3V3
- SRAM
- 128KB x8 x 2 BANKS (0 & 1)
- IS63LV1024/IDT71V124 - 15nS
- OC
- H = RELOAD DISABLED
- H = PROGRAMMED
- RESISTOR FOR 3.3V OPERATION
- TDI, TDO, TCK AND TMS ALL REQUIRE SERIES
- (XAPP453-P13)
- (near U3#1) VCCAUX = 2V5
- (near R35) H = PROGRAMMED (LOADED)
- LOW BY DEFAULT
- [7.159MHZ]
- [M2]
- (near U11) DISABLED DURING
- FPGA CONFIG
- (near U11) APPLE II BUS
- (near U3#1) BANK 0, 1, 2 & 3 = 3V3
- INPUT ONLY
- SPI
- M0, M1, M2
- XC3S250E
- XC3S500E
- GLOBAL CLOCK ALLOCATIONS
- DCM X1Y0 INPUT
- DCM X0Y1 INPUT
- [PULLED UP AT INTERFACE]
- DO/MISO
- DIN/MOSI
- CS
- SET EXTERNAL SPI MASTER
- BOOT FROM EXTERNAL SPI FLASH
- GCLK0 - 7.159MHZ
- GCLK0
- GCLK2 - PBIO24 - EXT CLOCK
- GCLK1
- GCLK2
- GCLK3
- GCLK 10 - PBIO26 - EXT CLOCK
- GCLK8
- GCLK 8 - 14.31818MHZ
- GCLK9
- GCLK10
- GCLK11
- SCLK
- M2 = L
- M1 = L
- EXTERNAL PULL UP
- DCM X1Y1 INPUT
- GCLK4 - PBIO21 - EXT CLOCK
- GCLK5 - PBIO22 - EXT CLOCK
- GCLK6 - PBIO23 - EXT CLOCK
- GCLK7 - CLK_EXT0 - EXT CLOCK
- DCM X0Y0 INPUT
- GCLK15 - PBIO25 - EXT CLOCK
- GCLK12
- GCLK13
- GCLK14
- GCLK15
- (UG332-P34)
- Device 			XC3S250E
  System Gates 		250K
  Logic Cells 		5,508
  Dedicated Multipliers 	12
  Common logic Blocks 	612
  Block RAM Bits 		216k (27.6KB)
  Distributed RAM Bits 	38k (4.8KB)
  User IO 		                 158 (32 Input Only)
  Min-Max DCM Input                  5MHz-300MHz
  DCMs 			 4
- Device 			XC3S500E
  System Gates 		500K
  Logic Cells 		10,476
  Dedicated Multipliers 	20
  Common logic Blocks 	1,164
  Block RAM Bits 		360k (45KB)
  Distributed RAM Bits 	73k (9.1KB)
  User IO 		                 158 (32 Input Only)
  Min-Max DCM Input                  5MHz-300MHz
  DCMs 			 4
- GCLK4
- GCLK5
- GCLK6
- GCLK7

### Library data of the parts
KFEST = CAP-NP: Capacitor, Ceramic, 1uF 10% 16V 0402 (1005) X7R
LED5 = DIO-LED-1S: LED, SMD Green 0603 (1608) 60mCd
R24-R28 R30-R35 = RES: Resistor, 4K7 1% 0402 (1005)
R29 = RES: Resistor, 47K 1% 0402 (1005)
U3#1 = XC3S500E-4PQ208C: IC SPARTAN-3E FPGA 500K 208-PQFP; EnablePinSwap: True
U11 = SN74LVC1G04DBV: IC SINGLE INVERTER-GATE SOT-23-5

## Sheet LEVELTRANSLATOR.SchDoc: AII BUS LEVEL TRANSLATORS
size A3; PageSetup: Record=PageOptions|CenterHorizontal=True|CenterVertical=True|PrintScale=0.73|XCorrection=1.00|YCorrection=1.00|PrintKind=0|BorderSize=5000000|LeftOffset=0|BottomOffset=0|Orientation=2|PaperLength=1000|PaperWidth=1000|Scale=100|PaperSource=7|PrintQuality=-4|MediaType=1|DitherType=10|PaperKind=A3|PrintScaleMode=1; CheckedBy: SRKH; Author: SRKH; Engineer: SRKH; DocumentNumber: 4; Revision: CB500E; SheetNumber: 4; SheetTotal: 18; DrawnBy: SRKH; Address1: WWW.APPLELOGIC.ORG
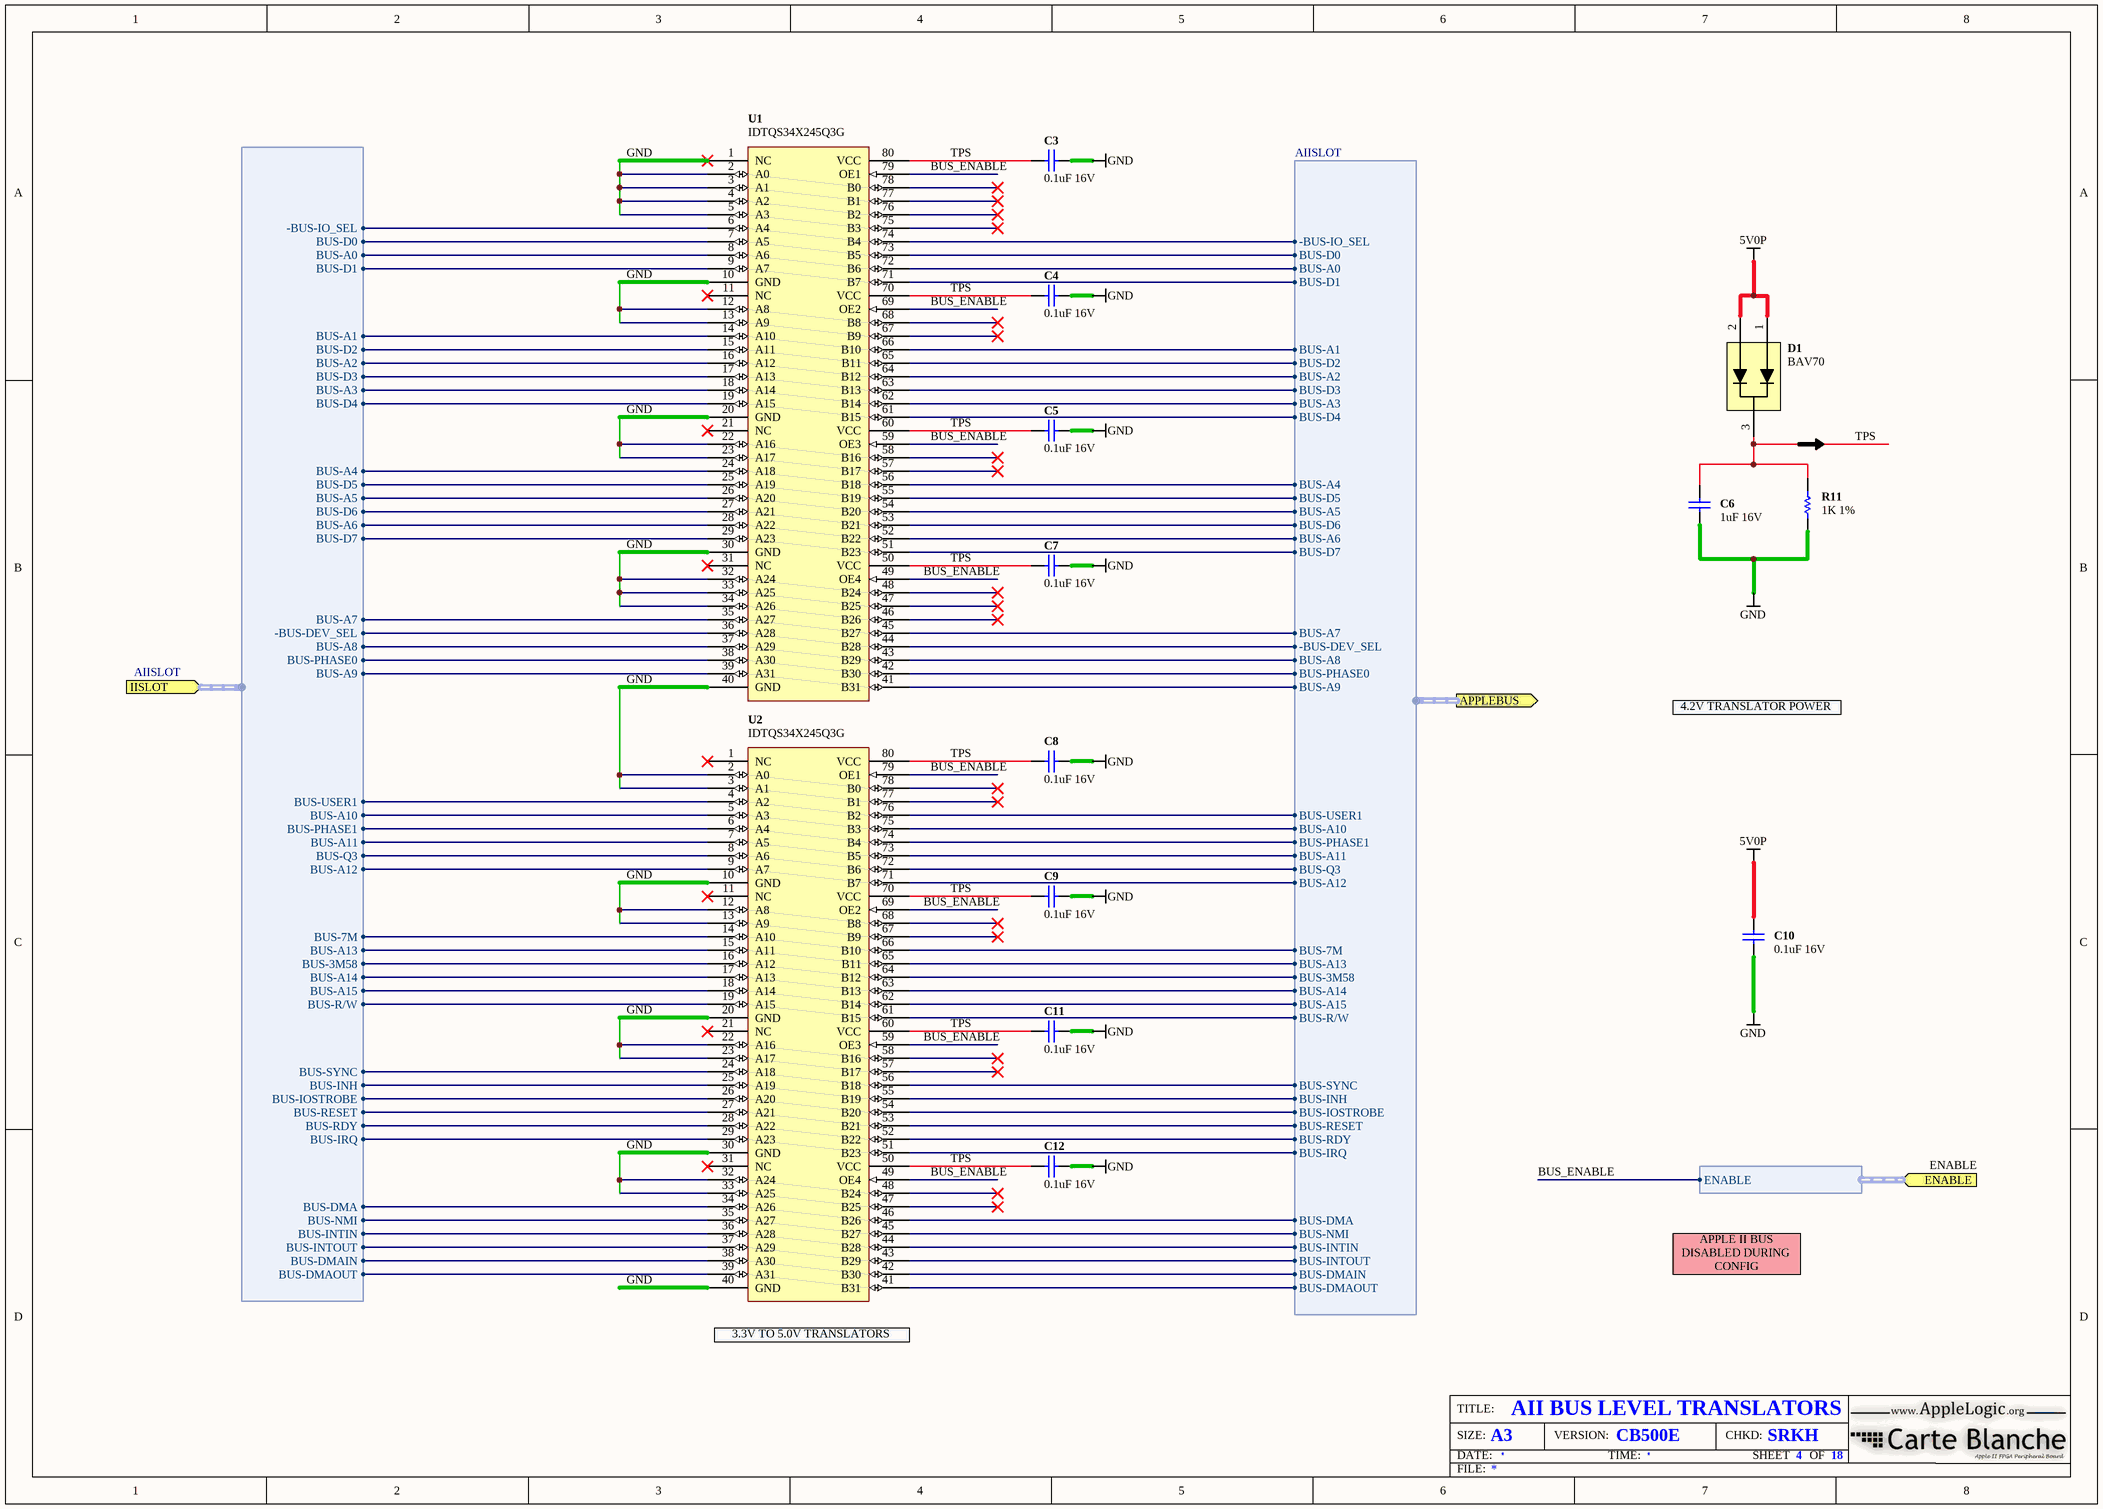
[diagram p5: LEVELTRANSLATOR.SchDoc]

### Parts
C3  0.1uF 16V  [CAPC1005-STAR]
C4  0.1uF 16V  [CAPC1005-STAR]
C5  0.1uF 16V  [CAPC1005-STAR]
C6  1uF 16V  [CAPC1005-STAR]
C7  0.1uF 16V  [CAPC1005-STAR]
C8  0.1uF 16V  [CAPC1005-STAR]
C9  0.1uF 16V  [CAPC1005-STAR]
C10  0.1uF 16V  [CAPC1005-STAR]
C11  0.1uF 16V  [CAPC1005-STAR]
C12  0.1uF 16V  [CAPC1005-STAR]
D1  BAV70  [SOT95P230-3]
R11  1K 1%  [RESC1005-STAR]
U1  IDTQS34X245Q3G  [QVSOP80]
U2  IDTQS34X245Q3G  [QVSOP80]

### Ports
APPLEBUS (harness AIISLOT), ENABLE (harness ENABLE), IISLOT (harness AIISLOT)

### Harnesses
AIISLOT: -BUS-DEV_SEL, BUS-PHASE0, BUS-USER1, BUS-PHASE1, BUS-Q3, BUS-7M, BUS-3M58, BUS-INH, BUS-RESET, BUS-IRQ, BUS-NMI, BUS-DMA, BUS-RDY, BUS-IOSTROBE, BUS-SYNC, BUS-R/W, BUS-A15, BUS-A14, BUS-A13, BUS-A12, BUS-A11, BUS-A10, BUS-A9, BUS-A8, BUS-A7, BUS-A6, BUS-A5, BUS-A4, BUS-A3, BUS-A2, BUS-A1, BUS-A0, -BUS-IO_SEL, BUS-D0, BUS-D1, BUS-D2, BUS-D3, BUS-D4, BUS-D5, BUS-D6, BUS-D7, BUS-DMAIN, BUS-DMAOUT, BUS-INTIN, BUS-INTOUT
ENABLE: ENABLE

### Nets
5V0P: C10.1 D1.1 D1.2
GND: C3.2 C4.2 C5.2 C6.2 C7.2 C8.2 C9.2 C10.2 C11.2 C12.2 R11.2 U1.1(NC) U1.2(A0) U1.3(A1) U1.4(A2) U1.5(A3) U1.10(GND) U1.12(A8) U1.13(A9) U1.20(GND) U1.22(A16) U1.23(A17) U1.30(GND) U1.32(A24) U1.33(A25) U1.34(A26) U1.40(GND) U2.2(A0) U2.3(A1) U2.10(GND) U2.12(A8) U2.13(A9) U2.20(GND) U2.22(A16) U2.23(A17) U2.30(GND) U2.32(A24) U2.33(A25) U2.40(GND)
AIIB.-BUS-DEV_SEL: U1.44(B28) ; port APPLEBUS.-BUS-DEV_SEL
AIIB.-BUS-IO_SEL: U1.74(B4) ; port APPLEBUS.-BUS-IO_SEL
AIIB.BUS-3M58: U2.64(B12) ; port APPLEBUS.BUS-3M58
AIIB.BUS-7M: U2.66(B10) ; port APPLEBUS.BUS-7M
AIIB.BUS-A0: U1.72(B6) ; port APPLEBUS.BUS-A0
AIIB.BUS-A1: U1.66(B10) ; port APPLEBUS.BUS-A1
AIIB.BUS-A2: U1.64(B12) ; port APPLEBUS.BUS-A2
AIIB.BUS-A3: U1.62(B14) ; port APPLEBUS.BUS-A3
AIIB.BUS-A4: U1.56(B18) ; port APPLEBUS.BUS-A4
AIIB.BUS-A5: U1.54(B20) ; port APPLEBUS.BUS-A5
AIIB.BUS-A6: U1.52(B22) ; port APPLEBUS.BUS-A6
AIIB.BUS-A7: U1.45(B27) ; port APPLEBUS.BUS-A7
AIIB.BUS-A8: U1.43(B29) ; port APPLEBUS.BUS-A8
AIIB.BUS-A9: U1.41(B31) ; port APPLEBUS.BUS-A9
AIIB.BUS-A10: U2.75(B3) ; port APPLEBUS.BUS-A10
AIIB.BUS-A11: U2.73(B5) ; port APPLEBUS.BUS-A11
AIIB.BUS-A12: U2.71(B7) ; port APPLEBUS.BUS-A12
AIIB.BUS-A13: U2.65(B11) ; port APPLEBUS.BUS-A13
AIIB.BUS-A14: U2.63(B13) ; port APPLEBUS.BUS-A14
AIIB.BUS-A15: U2.62(B14) ; port APPLEBUS.BUS-A15
AIIB.BUS-D0: U1.73(B5) ; port APPLEBUS.BUS-D0
AIIB.BUS-D1: U1.71(B7) ; port APPLEBUS.BUS-D1
AIIB.BUS-D2: U1.65(B11) ; port APPLEBUS.BUS-D2
AIIB.BUS-D3: U1.63(B13) ; port APPLEBUS.BUS-D3
AIIB.BUS-D4: U1.61(B15) ; port APPLEBUS.BUS-D4
AIIB.BUS-D5: U1.55(B19) ; port APPLEBUS.BUS-D5
AIIB.BUS-D6: U1.53(B21) ; port APPLEBUS.BUS-D6
AIIB.BUS-D7: U1.51(B23) ; port APPLEBUS.BUS-D7
AIIB.BUS-DMA: U2.46(B26) ; port APPLEBUS.BUS-DMA
AIIB.BUS-DMAIN: U2.42(B30) ; port APPLEBUS.BUS-DMAIN
AIIB.BUS-DMAOUT: U2.41(B31) ; port APPLEBUS.BUS-DMAOUT
AIIB.BUS-INH: U2.55(B19) ; port APPLEBUS.BUS-INH
AIIB.BUS-INTIN: U2.44(B28) ; port APPLEBUS.BUS-INTIN
AIIB.BUS-INTOUT: U2.43(B29) ; port APPLEBUS.BUS-INTOUT
AIIB.BUS-IOSTROBE: U2.54(B20) ; port APPLEBUS.BUS-IOSTROBE
AIIB.BUS-IRQ: U2.51(B23) ; port APPLEBUS.BUS-IRQ
AIIB.BUS-NMI: U2.45(B27) ; port APPLEBUS.BUS-NMI
AIIB.BUS-PHASE0: U1.42(B30) ; port APPLEBUS.BUS-PHASE0
AIIB.BUS-PHASE1: U2.74(B4) ; port APPLEBUS.BUS-PHASE1
AIIB.BUS-Q3: U2.72(B6) ; port APPLEBUS.BUS-Q3
AIIB.BUS-R/W: U2.61(B15) ; port APPLEBUS.BUS-R/W
AIIB.BUS-RDY: U2.52(B22) ; port APPLEBUS.BUS-RDY
AIIB.BUS-RESET: U2.53(B21) ; port APPLEBUS.BUS-RESET
AIIB.BUS-SYNC: U2.56(B18) ; port APPLEBUS.BUS-SYNC
AIIB.BUS-USER1: U2.76(B2) ; port APPLEBUS.BUS-USER1
AIIS.-BUS-DEV_SEL: U1.36(A28) ; port IISLOT.-BUS-DEV_SEL
AIIS.-BUS-IO_SEL: U1.6(A4) ; port IISLOT.-BUS-IO_SEL
AIIS.BUS-3M58: U2.16(A12) ; port IISLOT.BUS-3M58
AIIS.BUS-7M: U2.14(A10) ; port IISLOT.BUS-7M
AIIS.BUS-A0: U1.8(A6) ; port IISLOT.BUS-A0
AIIS.BUS-A1: U1.14(A10) ; port IISLOT.BUS-A1
AIIS.BUS-A2: U1.16(A12) ; port IISLOT.BUS-A2
AIIS.BUS-A3: U1.18(A14) ; port IISLOT.BUS-A3
AIIS.BUS-A4: U1.24(A18) ; port IISLOT.BUS-A4
AIIS.BUS-A5: U1.26(A20) ; port IISLOT.BUS-A5
AIIS.BUS-A6: U1.28(A22) ; port IISLOT.BUS-A6
AIIS.BUS-A7: U1.35(A27) ; port IISLOT.BUS-A7
AIIS.BUS-A8: U1.37(A29) ; port IISLOT.BUS-A8
AIIS.BUS-A9: U1.39(A31) ; port IISLOT.BUS-A9
AIIS.BUS-A10: U2.5(A3) ; port IISLOT.BUS-A10
AIIS.BUS-A11: U2.7(A5) ; port IISLOT.BUS-A11
AIIS.BUS-A12: U2.9(A7) ; port IISLOT.BUS-A12
AIIS.BUS-A13: U2.15(A11) ; port IISLOT.BUS-A13
AIIS.BUS-A14: U2.17(A13) ; port IISLOT.BUS-A14
AIIS.BUS-A15: U2.18(A14) ; port IISLOT.BUS-A15
AIIS.BUS-D0: U1.7(A5) ; port IISLOT.BUS-D0
AIIS.BUS-D1: U1.9(A7) ; port IISLOT.BUS-D1
AIIS.BUS-D2: U1.15(A11) ; port IISLOT.BUS-D2
AIIS.BUS-D3: U1.17(A13) ; port IISLOT.BUS-D3
AIIS.BUS-D4: U1.19(A15) ; port IISLOT.BUS-D4
AIIS.BUS-D5: U1.25(A19) ; port IISLOT.BUS-D5
AIIS.BUS-D6: U1.27(A21) ; port IISLOT.BUS-D6
AIIS.BUS-D7: U1.29(A23) ; port IISLOT.BUS-D7
AIIS.BUS-DMA: U2.34(A26) ; port IISLOT.BUS-DMA
AIIS.BUS-DMAIN: U2.38(A30) ; port IISLOT.BUS-DMAIN
AIIS.BUS-DMAOUT: U2.39(A31) ; port IISLOT.BUS-DMAOUT
AIIS.BUS-INH: U2.25(A19) ; port IISLOT.BUS-INH
AIIS.BUS-INTIN: U2.36(A28) ; port IISLOT.BUS-INTIN
AIIS.BUS-INTOUT: U2.37(A29) ; port IISLOT.BUS-INTOUT
AIIS.BUS-IOSTROBE: U2.26(A20) ; port IISLOT.BUS-IOSTROBE
AIIS.BUS-IRQ: U2.29(A23) ; port IISLOT.BUS-IRQ
AIIS.BUS-NMI: U2.35(A27) ; port IISLOT.BUS-NMI
AIIS.BUS-PHASE0: U1.38(A30) ; port IISLOT.BUS-PHASE0
AIIS.BUS-PHASE1: U2.6(A4) ; port IISLOT.BUS-PHASE1
AIIS.BUS-Q3: U2.8(A6) ; port IISLOT.BUS-Q3
AIIS.BUS-R/W: U2.19(A15) ; port IISLOT.BUS-R/W
AIIS.BUS-RDY: U2.28(A22) ; port IISLOT.BUS-RDY
AIIS.BUS-RESET: U2.27(A21) ; port IISLOT.BUS-RESET
AIIS.BUS-SYNC: U2.24(A18) ; port IISLOT.BUS-SYNC
AIIS.BUS-USER1: U2.4(A2) ; port IISLOT.BUS-USER1
BUS_ENABLE: U1.49(OE4) U1.59(OE3) U1.69(OE2) U1.79(OE1) U2.49(OE4) U2.59(OE3) U2.69(OE2) U2.79(OE1) ; port ENABLE.ENABLE
TPS: C3.1 C4.1 C5.1 C6.1 C7.1 C8.1 C9.1 C11.1 C12.1 D1.3 R11.1 U1.50(VCC) U1.60(VCC) U1.70(VCC) U1.80(VCC) U2.50(VCC) U2.60(VCC) U2.70(VCC) U2.80(VCC)

Not connected (* = marked no-connect by the designer): U1 11(NC)* 21(NC)* 31(NC)* 46(B26)* 47(B25)* 48(B24)* 57(B17)* 58(B16)* 67(B9)* 68(B8)* 75(B3)* 76(B2)* 77(B1)* 78(B0)*; U2 1(NC)* 11(NC)* 21(NC)* 31(NC)* 47(B25)* 48(B24)* 57(B17)* 58(B16)* 67(B9)* 68(B8)* 77(B1)* 78(B0)*

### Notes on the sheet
- 4.2V TRANSLATOR POWER
- DISABLED DURING
- APPLE II BUS
- CONFIG
- (near U2) 3.3V TO 5.0V TRANSLATORS

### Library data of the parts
C3-C12 = CAP-NP: as KFEST on sheet XC3S500E-4PQ208
D1 = BAV70: BAV70, SOT-23 Shottky Diode Pair Common Cathode
R11 = RES: Resistor, 4K7 1% 0402 (1005)
U1 U2 = IDTQS34XVH245: IC BUS SWITCH 32BIT CMOS 80QVSOP

## Sheet PERIPHERAL.SchDoc: PERIPHERAL BD INTERFACE
size A4; PageSetup: Record=PageOptions|CenterHorizontal=True|CenterVertical=True|PrintScale=0.73|XCorrection=1.00|YCorrection=1.00|PrintKind=0|BorderSize=5000000|LeftOffset=0|BottomOffset=0|Orientation=2|PaperLength=1000|PaperWidth=1000|Scale=100|PaperSource=7|PrintQuality=-4|MediaType=1|DitherType=10|PaperKind=A3|PrintScaleMode=1; CheckedBy: SRKH; Author: SRKH; Engineer: SRKH; DocumentNumber: 7; Revision: CB500E; SheetNumber: 7; SheetTotal: 18; DrawnBy: SRKH; Address1: WWW.APPLELOGIC.ORG
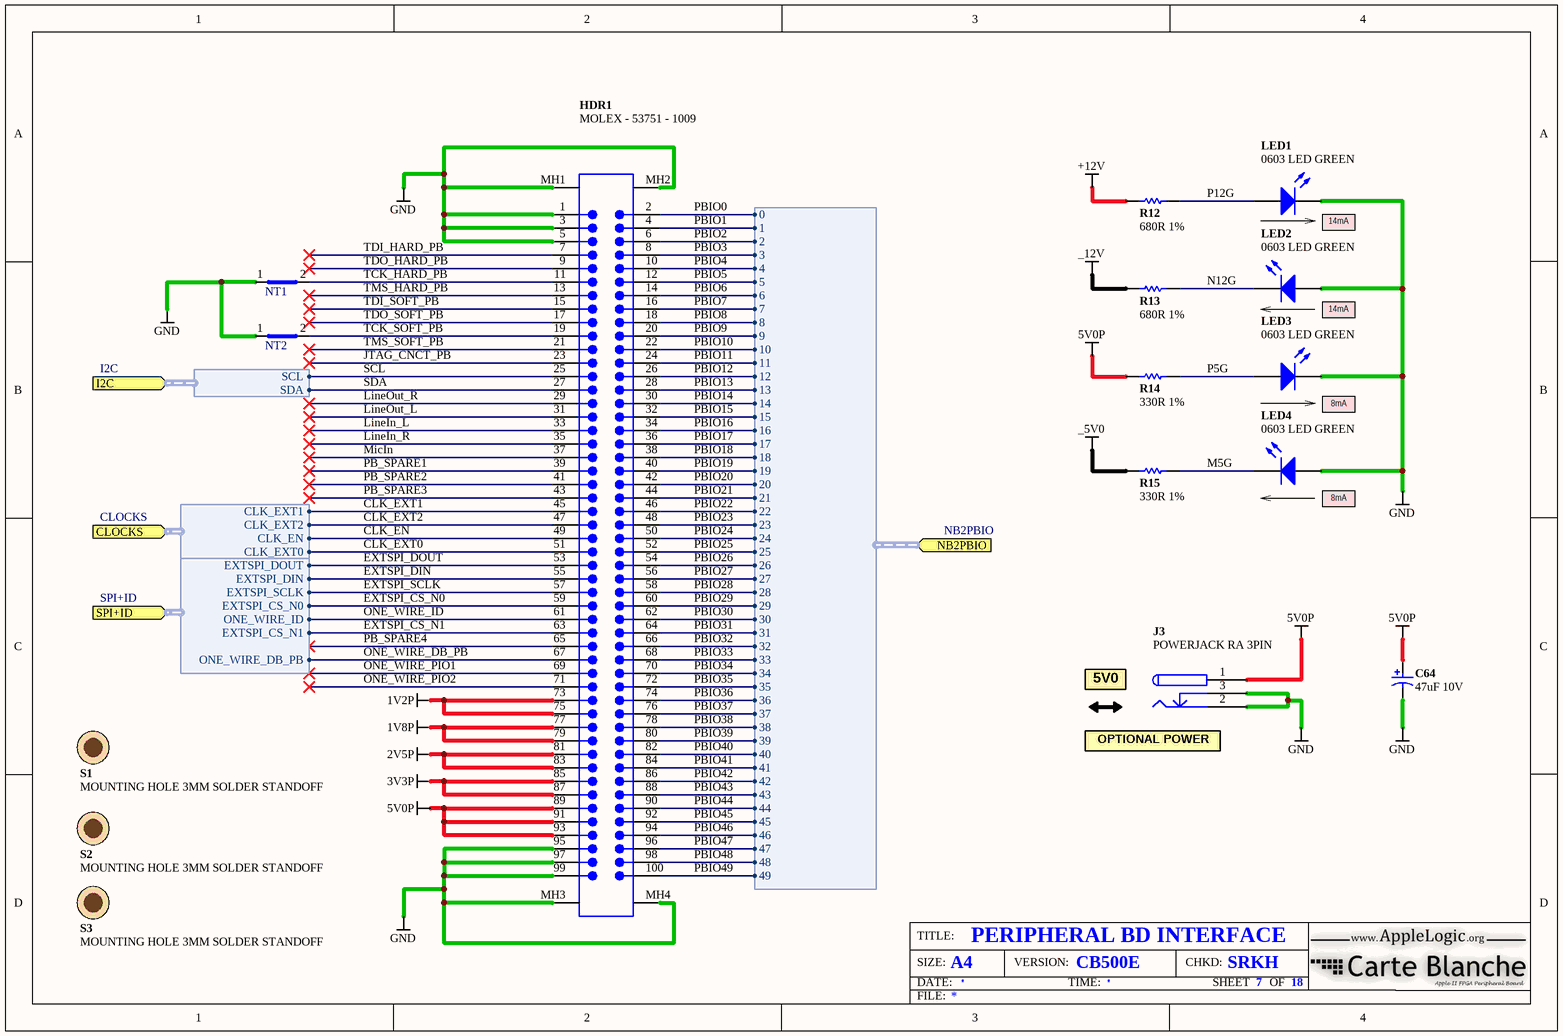
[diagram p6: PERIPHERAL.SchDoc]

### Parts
C64  47uF 10V  [CAPC3528-STAR]
HDR1  MOLEX - 53751 - 1009  [53751]
J3  POWERJACK RA 3PIN  [KLD-0202]
LED1  0603 LED GREEN  [0603LED_Kingbright_Green]
LED2  0603 LED GREEN  [0603LED_Kingbright_Green]
LED3  0603 LED GREEN  [0603LED_Kingbright_Green]
LED4  0603 LED GREEN  [0603LED_Kingbright_Green]
NT1  Net Tie SMT2  [NETTIE-SMT2-31X51]  (value not drawn)  (net tie, no BOM)
NT2  Net Tie SMT2  [NETTIE-SMT2-31X51]  (value not drawn)  (net tie, no BOM)
R12  680R 1%  [RESC1005-STAR]
R13  680R 1%  [RESC1005-STAR]
R14  330R 1%  [RESC1005-STAR]
R15  330R 1%  [RESC1005-STAR]
S1  MOUNTING HOLE 3MM SOLDER STANDOFF  [STANDOFF_SOLDER_3MM]
S2  MOUNTING HOLE 3MM SOLDER STANDOFF  [STANDOFF_SOLDER_3MM]
S3  MOUNTING HOLE 3MM SOLDER STANDOFF  [STANDOFF_SOLDER_3MM]

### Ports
CLOCKS (harness CLOCKS), I2C (harness I2C), NB2PBIO (harness NB2PBIO), SPI+ID (harness SPI+ID)

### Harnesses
I2C: SCL, SDA
CLOCKS: CLK_EXT2, CLK_EXT0, CLK_EXT1, CLK_EN
SPI+ID: EXTSPI_DIN, EXTSPI_CS_N0, EXTSPI_DOUT, EXTSPI_SCLK, ONE_WIRE_ID, EXTSPI_CS_N1, ONE_WIRE_DB_PB
NB2PBIO: 0, 1, 2, 3, 4, 5, 6, 7, 8, 9, 10, 11, 12, 13, 14, 15, 16, 17, 18, 19, 20, 21, 22, 23, 24, 25, 26, 27, 28, 29, 30, 31, 32, 33, 34, 35, 36, 37, 38, 39, 40, 41, 42, 43, 44, 45, 46, 47, 48, 49

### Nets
1V2P: HDR1.73 HDR1.75
1V8P: HDR1.77 HDR1.79
2V5P: HDR1.81 HDR1.83
3V3P: HDR1.85 HDR1.87
5V0P: C64.1 HDR1.89 HDR1.91 HDR1.93 J3.1 R14.2
+12V: R12.2
_5V0: R15.2
_12V: R13.2
GND: C64.2 HDR1.1 HDR1.3 HDR1.5 HDR1.95 HDR1.97 HDR1.99 HDR1.MH1 HDR1.MH2 HDR1.MH3 HDR1.MH4 J3.2 J3.3 LED1.2(K) LED2.1(A) LED3.2(K) LED4.1(A) NT1.1(Net1) NT2.1(Net1)
CLK_EN: HDR1.49 ; port CLOCKS.CLK_EN
CLK_EXT0: HDR1.51 ; port CLOCKS.CLK_EXT0
CLK_EXT1: HDR1.45 ; port CLOCKS.CLK_EXT1
CLK_EXT2: HDR1.47 ; port CLOCKS.CLK_EXT2  [project net VGA.RED0]
EXTSPI_CS_N0: HDR1.59 ; port SPI+ID.EXTSPI_CS_N0
EXTSPI_CS_N1: HDR1.63 ; port SPI+ID.EXTSPI_CS_N1
EXTSPI_DIN: HDR1.55 ; port SPI+ID.EXTSPI_DIN  [project net ROM.DIN]
EXTSPI_DOUT: HDR1.53 ; port SPI+ID.EXTSPI_DOUT  [project net ROM.DOUT]
EXTSPI_SCLK: HDR1.57 ; port SPI+ID.EXTSPI_SCLK  [project net ROM.SCLK]
JTAG_CNCT_PB: HDR1.23
LineIn_L: HDR1.33
LineIn_R: HDR1.35
LineOut_L: HDR1.31
LineOut_R: HDR1.29
M5G: LED4.2(K) R15.1
MicIn: HDR1.37
N12G: LED2.2(K) R13.1
ONE_WIRE_DB_PB: HDR1.61 HDR1.67 ; port SPI+ID.ONE_WIRE_ID, port SPI+ID.ONE_WIRE_DB_PB  [also labelled ONE_WIRE_ID]
ONE_WIRE_PIO1: HDR1.69
ONE_WIRE_PIO2: HDR1.71
P5G: LED3.1(A) R14.1
P12G: LED1.1(A) R12.1
PB_SPARE1: HDR1.39
PB_SPARE2: HDR1.41
PB_SPARE3: HDR1.43
PB_SPARE4: HDR1.65
PBIO0: HDR1.2 ; port NB2PBIO.0  [project net VGA.GREEN0]
PBIO1: HDR1.4 ; port NB2PBIO.1  [project net VGA.GREEN1]
PBIO2: HDR1.6 ; port NB2PBIO.2  [project net VGA.BLUE0]
PBIO3: HDR1.8 ; port NB2PBIO.3  [project net VGA.BLUE1]
PBIO4: HDR1.10 ; port NB2PBIO.4  [project net VGA.RED1]
PBIO5: HDR1.12 ; port NB2PBIO.5  [project net IDE.D10]
PBIO6: HDR1.14 ; port NB2PBIO.6  [project net IDE.RESET]
PBIO7: HDR1.16 ; port NB2PBIO.7  [project net IDE.D8]
PBIO8: HDR1.18 ; port NB2PBIO.8  [project net IDE.D6]
PBIO9: HDR1.20 ; port NB2PBIO.9  [project net IDE.D7]
PBIO10: HDR1.22 ; port NB2PBIO.10  [project net IDE.D9]
PBIO11: HDR1.24 ; port NB2PBIO.11  [project net IDE.D11]
PBIO12: HDR1.26 ; port NB2PBIO.12  [project net IDE.D12]
PBIO13: HDR1.28 ; port NB2PBIO.13  [project net IDE.D4]
PBIO14: HDR1.30 ; port NB2PBIO.14  [project net IDE.D3]
PBIO15: HDR1.32 ; port NB2PBIO.15  [project net IDE.D2]
PBIO16: HDR1.34 ; port NB2PBIO.16  [project net IDE.D5]
PBIO17: HDR1.36 ; port NB2PBIO.17  [project net IDE.D13]
PBIO18: HDR1.38 ; port NB2PBIO.18  [project net IDE.DMACK]
PBIO19: HDR1.40 ; port NB2PBIO.19  [project net IDE.D14]
PBIO20: HDR1.42 ; port NB2PBIO.20  [project net IDE.D0]
PBIO21: HDR1.44 ; port NB2PBIO.21  [project net IDE.IOWR]
PBIO22: HDR1.46 ; port NB2PBIO.22  [project net IDE.CSEL]
PBIO23: HDR1.48 ; port NB2PBIO.23  [project net IDE.IORD]
PBIO24: HDR1.50 ; port NB2PBIO.24  [project net IDE.A0]
PBIO25: HDR1.52 ; port NB2PBIO.25  [project net IDE.D1]
PBIO26: HDR1.54 ; port NB2PBIO.26  [project net IDE.D15]
PBIO27: HDR1.56 ; port NB2PBIO.27  [project net IDE.CS1]
PBIO28: HDR1.58 ; port NB2PBIO.28  [project net IDE.DASP]
PBIO29: HDR1.60 ; port NB2PBIO.29
PBIO30: HDR1.62 ; port NB2PBIO.30
PBIO31: HDR1.64 ; port NB2PBIO.31
PBIO32: HDR1.66 ; port NB2PBIO.32
PBIO33: HDR1.68 ; port NB2PBIO.33
PBIO34: HDR1.70 ; port NB2PBIO.34
PBIO35: HDR1.72 ; port NB2PBIO.35
PBIO36: HDR1.74 ; port NB2PBIO.36
PBIO37: HDR1.76 ; port NB2PBIO.37
PBIO38: HDR1.78 ; port NB2PBIO.38
PBIO39: HDR1.80 ; port NB2PBIO.39
PBIO40: HDR1.82 ; port NB2PBIO.40  [project net IDE.A2]
PBIO41: HDR1.84 ; port NB2PBIO.41  [project net IDE.PDIAG]
PBIO42: HDR1.86 ; port NB2PBIO.42  [project net IDE.IOCS16]
PBIO43: HDR1.88 ; port NB2PBIO.43  [project net IDE.A1]
PBIO44: HDR1.90 ; port NB2PBIO.44  [project net IDE.CS0]
PBIO45: HDR1.92 ; port NB2PBIO.45  [project net VGA.HSYNC]
PBIO46: HDR1.94 ; port NB2PBIO.46  [project net VGA.VSYNC]
PBIO47: HDR1.96 ; port NB2PBIO.47  [project net SD.DAT1]
PBIO48: HDR1.98 ; port NB2PBIO.48  [project net SD.DAT2]
PBIO49: HDR1.100 ; port NB2PBIO.49  [project net SD.DAT3]
SCL: HDR1.25 ; port I2C.SCL  [project net VGA.SCL]
SDA: HDR1.27 ; port I2C.SDA  [project net VGA.SDA]
TCK_HARD_PB: HDR1.11 NT1.2(Net2)
TCK_SOFT_PB: HDR1.19 NT2.2(Net2)
TDI_HARD_PB: HDR1.7
TDI_SOFT_PB: HDR1.15
TDO_HARD_PB: HDR1.9
TDO_SOFT_PB: HDR1.17
TMS_HARD_PB: HDR1.13
TMS_SOFT_PB: HDR1.21

Not connected (* = marked no-connect by the designer): S1 1; S2 1; S3 1

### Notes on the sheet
- (near LED1) 14mA
- (near LED2) 14mA
- (near LED3) 8mA
- (near LED4) 8mA
- 5V0
- (near J3) OPTIONAL POWER

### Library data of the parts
C64 = CAP-P: as C1 on sheet APPLEIISLOT
HDR1 = CON-DOCKSTAT-100-F-STR: Connector, MOLEX - 53751 - 1009
J3 = CON-POWERJACK-3: Connector, RA 3 Conductor Power Jack
LED1-LED4 = DIO-LED-1S: LED, SMD Green 0603 (1608) 60mCd
NT1 NT2 = NETTIE-SMT2: Net-Tie, Surface Mount, 2 x 0.4mm x 0.2mm SMT Pads - For 0.2mm Track
R12-R15 = RES: Resistor, 4K7 1% 0402 (1005)
S1-S3 = MOUNTING_HOLE_3MM_STANDOFF: Solder Standoff, M3 Screw, Gold Plated, Round Pad

## Sheet PSU_1084_1V2.SchDoc: 1V2 POWER SUPPLY
size A4; CheckedBy: SRKH; Author: SRKH; Engineer: SRKH; DocumentNumber: 6; Revision: CB500E; SheetNumber: 6; SheetTotal: 18; DrawnBy: SRKH; Address1: WWW.APPLELOGIC.ORG; PageSetup: Record=PageOptions|CenterHorizontal=True|CenterVertical=True|PrintScale=0.73|XCorrection=1.00|YCorrection=1.00|PrintKind=0|BorderSize=5000000|LeftOffset=0|BottomOffset=0|Orientation=2|PaperLength=1000|PaperWidth=1000|Scale=100|PaperSource=7|PrintQuality=-4|MediaType=1|DitherType=10|PaperKind=A3|PrintScaleMode=1
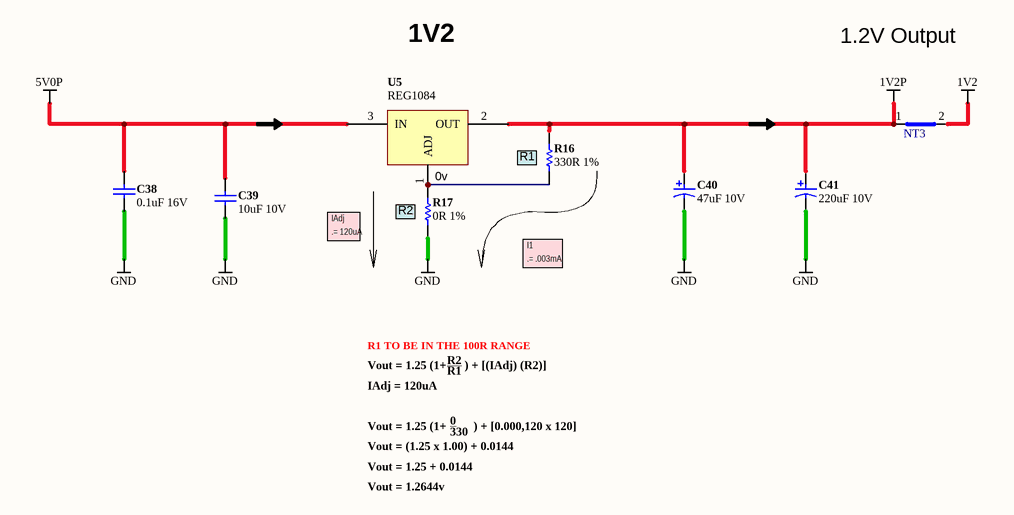
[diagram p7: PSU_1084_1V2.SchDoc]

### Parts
C38  0.1uF 16V  [CAPC1005-STAR]
C39  10uF 10V  [CAPC2012-STAR]
C40  47uF 10V  [CAPC3528-STAR]
C41  220uF 10V  [CAPC7343-STAR]
NT3  Net Tie SMT2  [NETTIE-SMT2-31X51]  (value not drawn)  (net tie, no BOM)
R16  330R 1%  [RESC1005-STAR]
R17  0R 1%  [RESC1005-STAR]
U5  REG1084  [TO-263]

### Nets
1V2: NT3.2(Net2)
1V2P: C40.1 C41.1 NT3.1(Net1) R16.2 U5.2(OUT)
5V0P: C38.1 C39.1 U5.3(IN)
GND: C38.2 C39.2 C40.2 C41.2 R17.1
NetR16_1: R16.1 R17.2 U5.1(ADJ)

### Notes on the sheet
- 1V2
- 1.2V Output
- (near U5) 0v
- (near R16) R1
- IAdj
- .= 120uA
- (near R17) R2
- I1
- .= .003mA
- Vout = 1.25 (1+      ) + [(IAdj) (R2)]
- IAdj = 120uA
- R1 TO BE IN THE 100R RANGE
- R2
- R1
- Vout = 1.25 (1+         ) + [0.000,120 x 120]
- Vout = (1.25 x 1.00) + 0.0144
- Vout = 1.25 + 0.0144
- 0
- 330
- Vout = 1.2644v

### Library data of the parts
C38 C39 = CAP-NP: as KFEST on sheet XC3S500E-4PQ208
C40 C41 = CAP-P: as C1 on sheet APPLEIISLOT
NT3 = NETTIE-SMT2: as NT1 on sheet PERIPHERAL
R16 R17 = RES: Resistor, 4K7 1% 0402 (1005)
U5 = REG1084: IC REG POSITIVE 5A LDO TO-263

## Sheet PSU_1084_1V8.SchDoc: 1V8 POWER SUPPLY
size A4; CheckedBy: SRKH; Author: SRKH; Engineer: SRKH; DocumentNumber: 8; Revision: CB500E; SheetNumber: 8; SheetTotal: 18; DrawnBy: SRKH; Address1: WWW.APPLELOGIC.ORG; PageSetup: Record=PageOptions|CenterHorizontal=True|CenterVertical=True|PrintScale=0.73|XCorrection=1.00|YCorrection=1.00|PrintKind=0|BorderSize=5000000|LeftOffset=0|BottomOffset=0|Orientation=2|PaperLength=1000|PaperWidth=1000|Scale=100|PaperSource=7|PrintQuality=-4|MediaType=1|DitherType=10|PaperKind=A3|PrintScaleMode=1
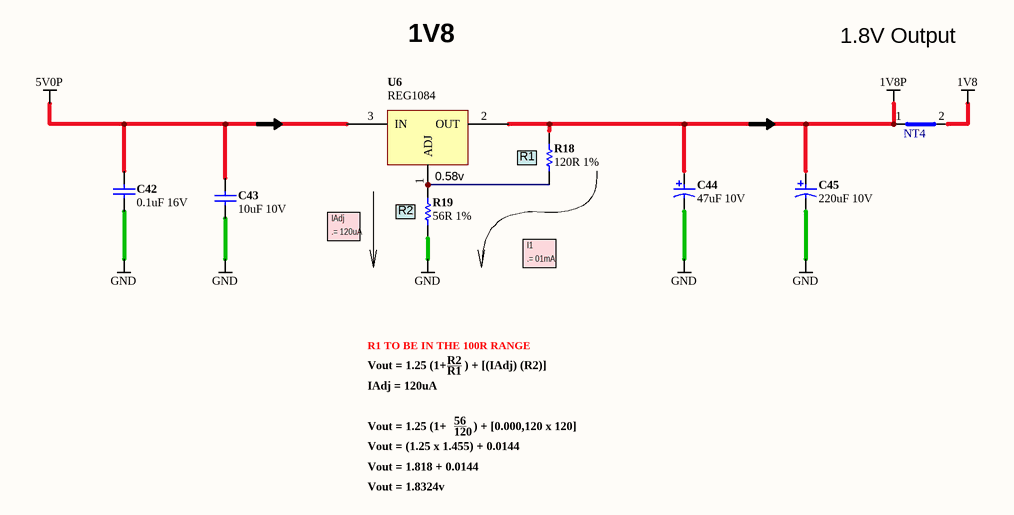
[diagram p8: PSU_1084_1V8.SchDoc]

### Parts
(Parts that share a designator on the sheet are numbered #1, #2 ... from top to bottom, then left to right.)
C42  0.1uF 16V  [CAPC1005-STAR]
C43  10uF 10V  [CAPC2012-STAR]
C44  47uF 10V  [CAPC3528-STAR]
C45  220uF 10V  [CAPC7343-STAR]
NT4  Net Tie SMT2  [NETTIE-SMT2-31X51]  (value not drawn)  (net tie, no BOM)
R18  120R 1%  [RESC1005-STAR]
R19  56R 1%  [RESC1005-STAR]
U6#1  REG1084  [TO-263]

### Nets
1V8: NT4.2(Net2)
1V8P: C44.1 C45.1 NT4.1(Net1) R18.2 U6#1.2(OUT)
5V0P: C42.1 C43.1 U6#1.3(IN)
GND: C42.2 C43.2 C44.2 C45.2 R19.1
NetR18_1: R18.1 R19.2 U6#1.1(ADJ)

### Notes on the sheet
- 1V8
- 1.8V Output
- (near U6#1) 0.58v
- (near R18) R1
- IAdj
- .= 120uA
- (near R19) R2
- I1
- .= 01mA
- Vout = 1.25 (1+      ) + [(IAdj) (R2)]
- IAdj = 120uA
- R1 TO BE IN THE 100R RANGE
- R2
- R1
- Vout = 1.25 (1+         ) + [0.000,120 x 120]
- Vout = (1.25 x 1.455) + 0.0144
- Vout = 1.818 + 0.0144
- 56
- 120
- Vout = 1.8324v

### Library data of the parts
C42 C43 = CAP-NP: as KFEST on sheet XC3S500E-4PQ208
C44 C45 = CAP-P: as C1 on sheet APPLEIISLOT
NT4 = NETTIE-SMT2: as NT1 on sheet PERIPHERAL
R18 R19 = RES: Resistor, 4K7 1% 0402 (1005)
U6#1 = REG1084: IC REG POSITIVE 5A LDO TO-263

## Sheet PSU_1084_2V5.SchDoc: 2V5 POWER SUPPLY
size A4; CheckedBy: SRKH; Author: SRKH; Engineer: SRKH; DocumentNumber: 10; Revision: CB500E; SheetNumber: 10; SheetTotal: 18; DrawnBy: SRKH; Address1: WWW.APPLELOGIC.ORG; PageSetup: Record=PageOptions|CenterHorizontal=True|CenterVertical=True|PrintScale=0.73|XCorrection=1.00|YCorrection=1.00|PrintKind=0|BorderSize=5000000|LeftOffset=0|BottomOffset=0|Orientation=2|PaperLength=1000|PaperWidth=1000|Scale=100|PaperSource=7|PrintQuality=-4|MediaType=1|DitherType=10|PaperKind=A3|PrintScaleMode=1
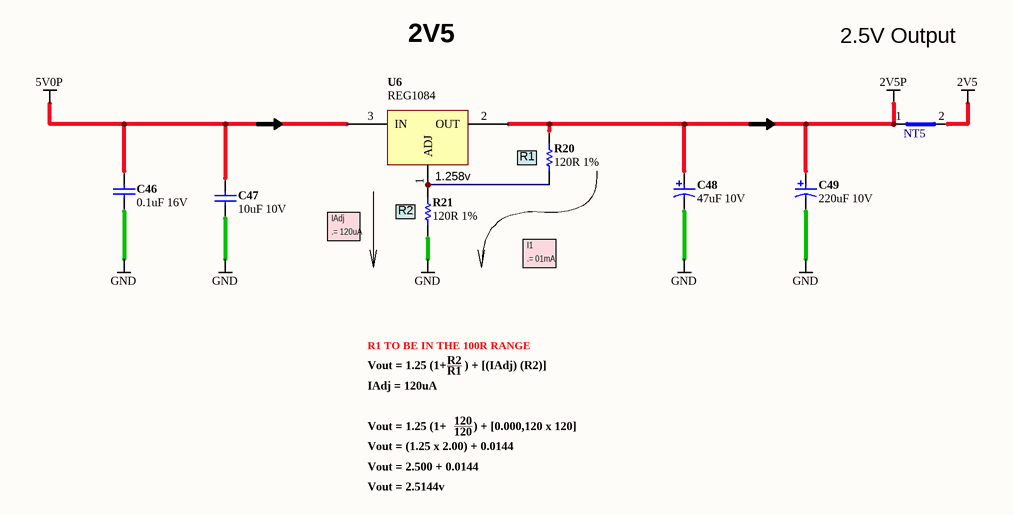
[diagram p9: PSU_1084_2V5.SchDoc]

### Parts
(Parts that share a designator on the sheet are numbered #1, #2 ... from top to bottom, then left to right.)
C46  0.1uF 16V  [CAPC1005-STAR]
C47  10uF 10V  [CAPC2012-STAR]
C48  47uF 10V  [CAPC3528-STAR]
C49  220uF 10V  [CAPC7343-STAR]
NT5  Net Tie SMT2  [NETTIE-SMT2-31X51]  (value not drawn)  (net tie, no BOM)
R20  120R 1%  [RESC1005-STAR]
R21  120R 1%  [RESC1005-STAR]
U6#2  REG1084  [TO-263]

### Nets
2V5: NT5.2(Net2)
2V5P: C48.1 C49.1 NT5.1(Net1) R20.2 U6#2.2(OUT)
5V0P: C46.1 C47.1 U6#2.3(IN)
GND: C46.2 C47.2 C48.2 C49.2 R21.1
NetR20_1: R20.1 R21.2 U6#2.1(ADJ)

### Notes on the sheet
- 2V5
- 2.5V Output
- (near U6#2) 1.258v
- (near R20) R1
- IAdj
- .= 120uA
- (near R21) R2
- I1
- .= 01mA
- Vout = 1.25 (1+      ) + [(IAdj) (R2)]
- IAdj = 120uA
- R1 TO BE IN THE 100R RANGE
- R2
- R1
- Vout = 1.25 (1+         ) + [0.000,120 x 120]
- Vout = (1.25 x 2.00) + 0.0144
- Vout = 2.500 + 0.0144
- 120
- Vout = 2.5144v

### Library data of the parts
C46 C47 = CAP-NP: as KFEST on sheet XC3S500E-4PQ208
C48 C49 = CAP-P: as C1 on sheet APPLEIISLOT
NT5 = NETTIE-SMT2: as NT1 on sheet PERIPHERAL
R20 R21 = RES: Resistor, 4K7 1% 0402 (1005)
U6#2 = REG1084: IC REG POSITIVE 5A LDO TO-263

## Sheet PSU_1084_3V3.SchDoc: 3V3 POWER SUPPLY
size A4; CheckedBy: SRKH; Author: SRKH; Engineer: SRKH; DocumentNumber: 9; Revision: CB500E; SheetNumber: 9; SheetTotal: 18; DrawnBy: SRKH; Address1: WWW.APPLELOGIC.ORG; PageSetup: Record=PageOptions|CenterHorizontal=True|CenterVertical=True|PrintScale=0.73|XCorrection=1.00|YCorrection=1.00|PrintKind=0|BorderSize=5000000|LeftOffset=0|BottomOffset=0|Orientation=2|PaperLength=1000|PaperWidth=1000|Scale=100|PaperSource=7|PrintQuality=-4|MediaType=1|DitherType=10|PaperKind=A3|PrintScaleMode=1
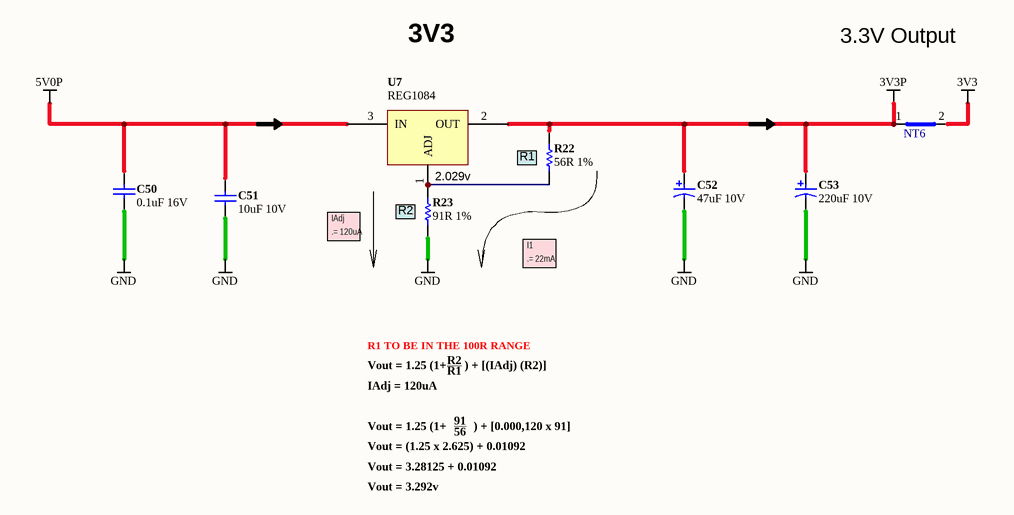
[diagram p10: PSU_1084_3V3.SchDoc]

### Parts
C50  0.1uF 16V  [CAPC1005-STAR]
C51  10uF 10V  [CAPC2012-STAR]
C52  47uF 10V  [CAPC3528-STAR]
C53  220uF 10V  [CAPC7343-STAR]
NT6  Net Tie SMT2  [NETTIE-SMT2-31X51]  (value not drawn)  (net tie, no BOM)
R22  56R 1%  [RESC1005-STAR]
R23  91R 1%  [RESC1005-STAR]
U7  REG1084  [TO-263]

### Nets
3V3: NT6.2(Net2)
3V3P: C52.1 C53.1 NT6.1(Net1) R22.2 U7.2(OUT)
5V0P: C50.1 C51.1 U7.3(IN)
GND: C50.2 C51.2 C52.2 C53.2 R23.1
NetR22_1: R22.1 R23.2 U7.1(ADJ)

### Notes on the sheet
- 3V3
- 3.3V Output
- (near U7) 2.029v
- (near R22) R1
- IAdj
- .= 120uA
- (near R23) R2
- I1
- .= 22mA
- Vout = 1.25 (1+      ) + [(IAdj) (R2)]
- IAdj = 120uA
- R1 TO BE IN THE 100R RANGE
- R2
- R1
- Vout = 1.25 (1+         ) + [0.000,120 x 91]
- Vout = (1.25 x 2.625) + 0.01092
- Vout = 3.28125 + 0.01092
- 91
- 56
- Vout = 3.292v

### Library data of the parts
C50 C51 = CAP-NP: as KFEST on sheet XC3S500E-4PQ208
C52 C53 = CAP-P: as C1 on sheet APPLEIISLOT
NT6 = NETTIE-SMT2: as NT1 on sheet PERIPHERAL
R22 R23 = RES: Resistor, 4K7 1% 0402 (1005)
U7 = REG1084: IC REG POSITIVE 5A LDO TO-263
